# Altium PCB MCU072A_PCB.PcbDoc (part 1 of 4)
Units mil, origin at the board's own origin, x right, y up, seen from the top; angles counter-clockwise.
Board outline 2661.1 x 1953.35 mil, 8 copper layers (Top Layer, Mid-Layer 2, Mid-Layer 3, Mid-Layer 4, Mid-Layer 5, Mid-Layer 6, Mid-Layer 7, Bottom Layer), stack 61.2 mil thick; 186 components, 165 nets, 716 pads, 419 vias.
Unrouted connection lines stored in the file: 1.
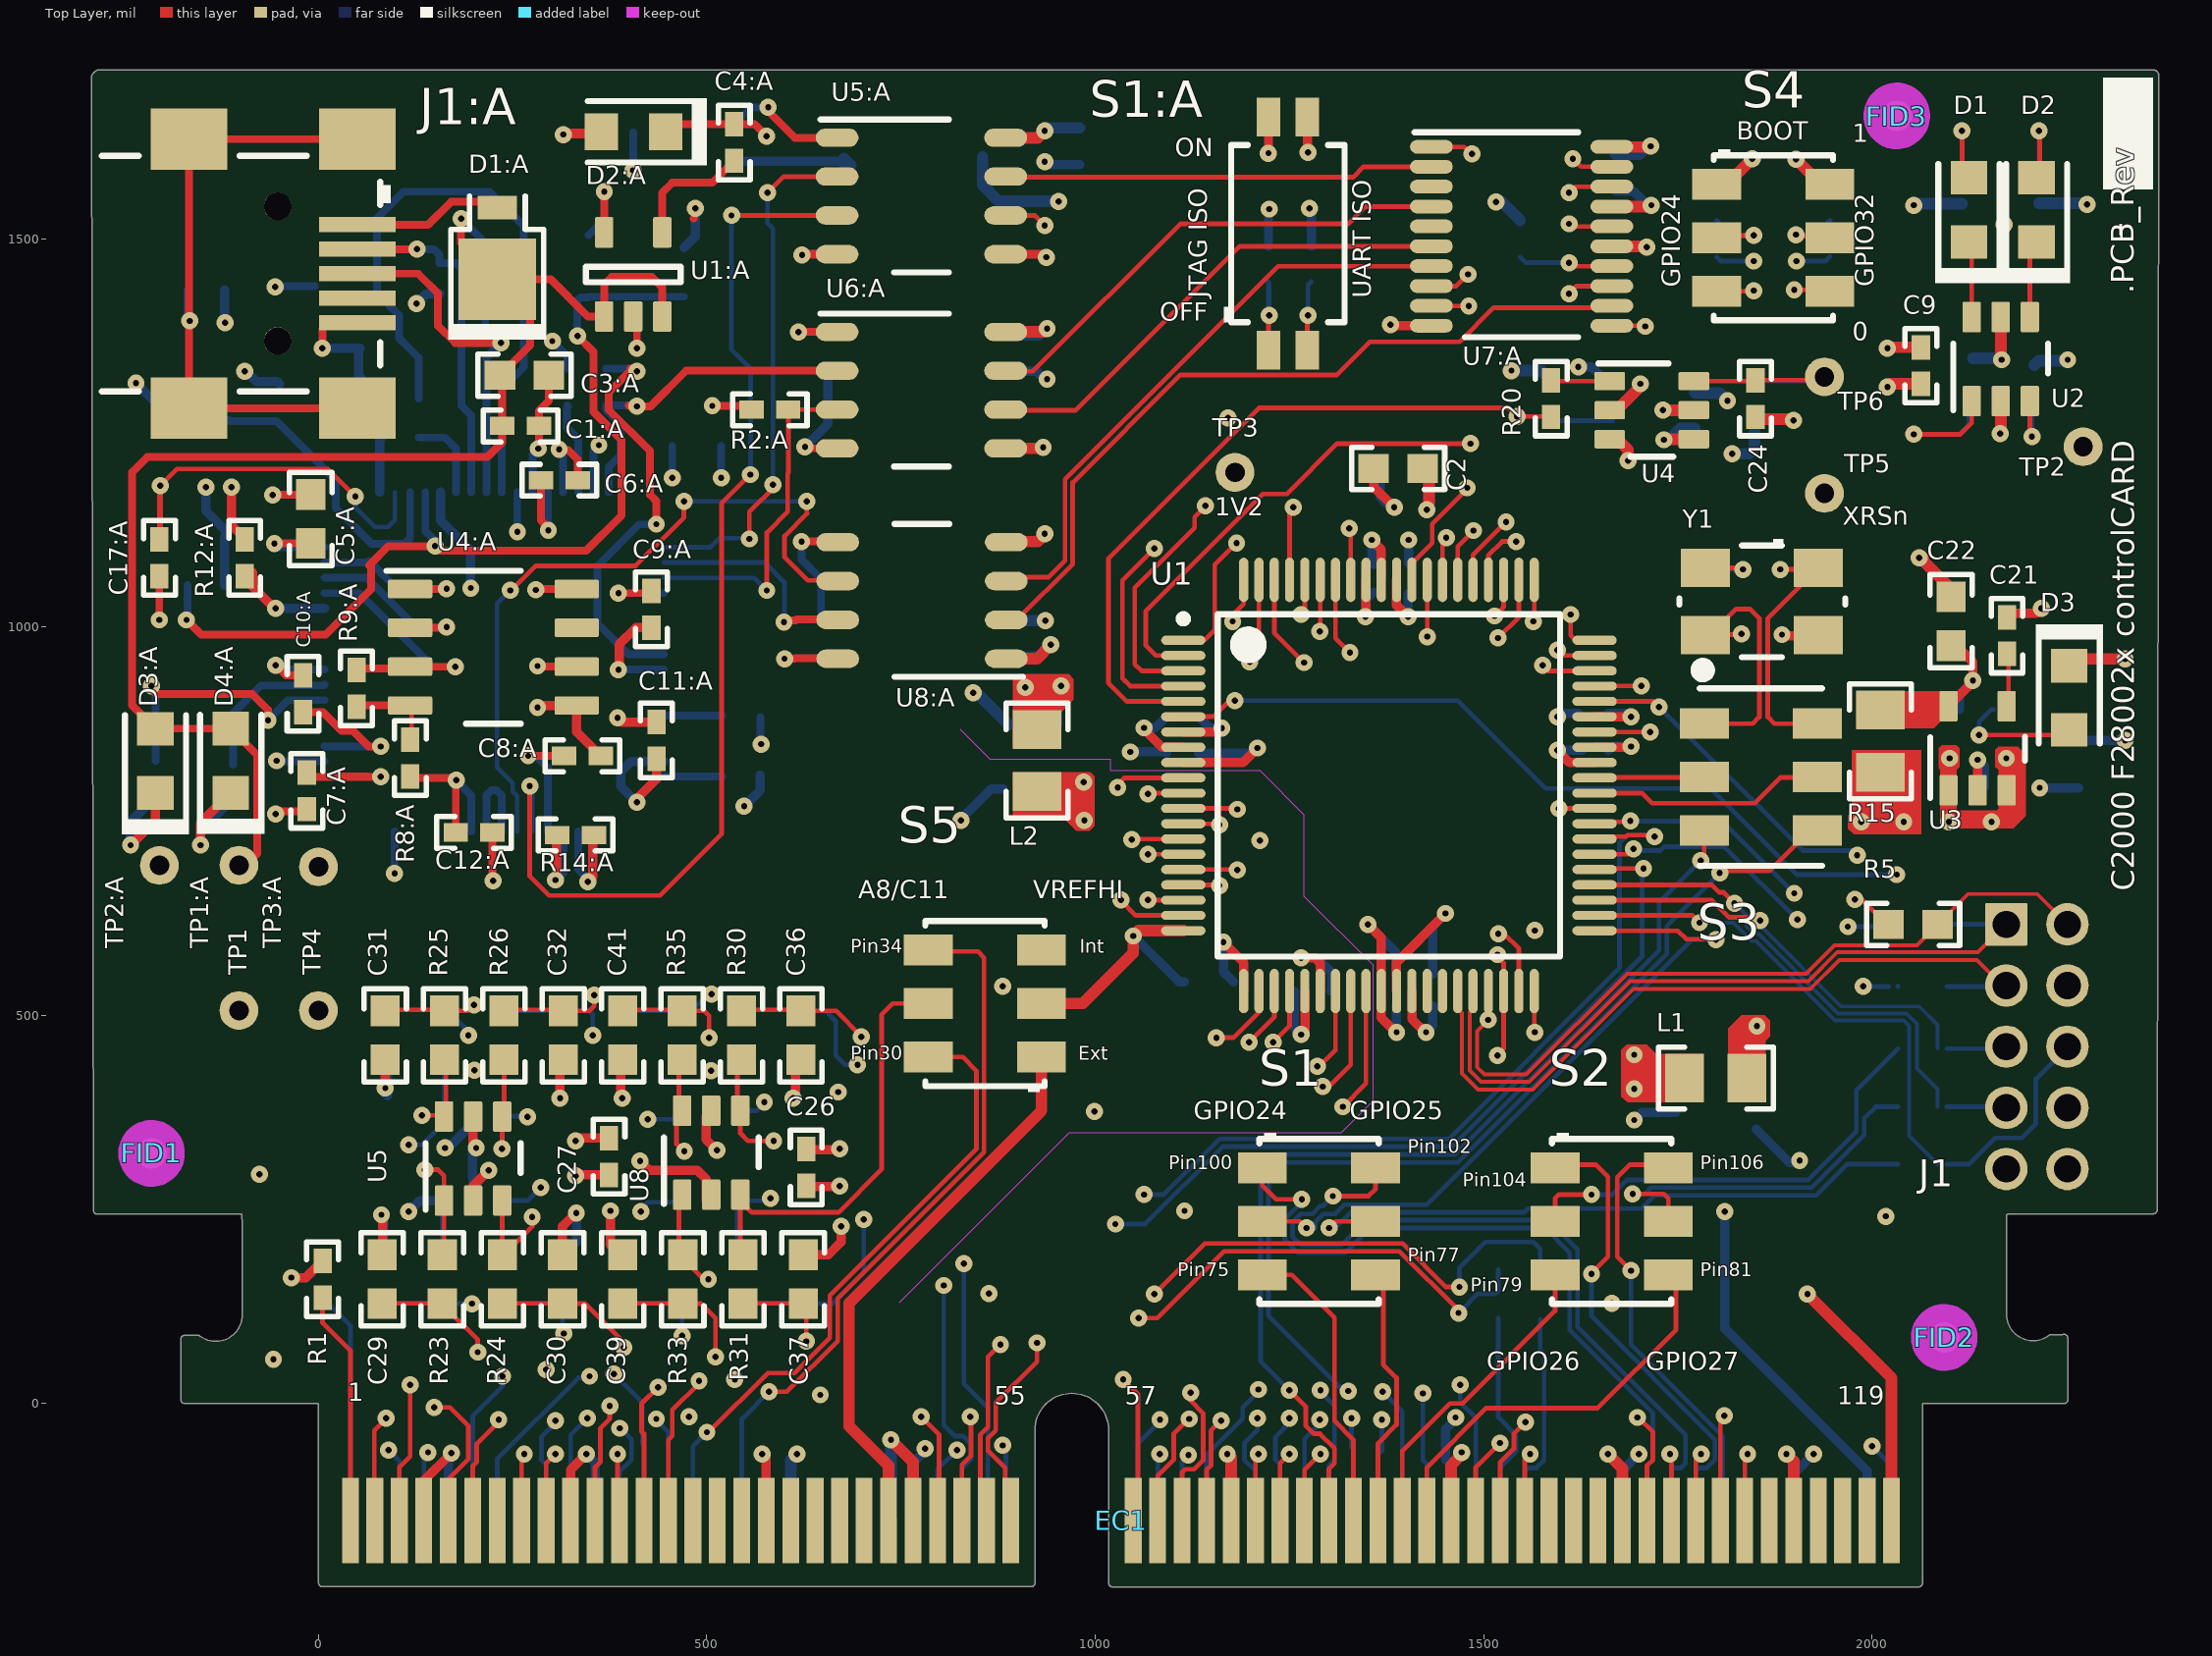
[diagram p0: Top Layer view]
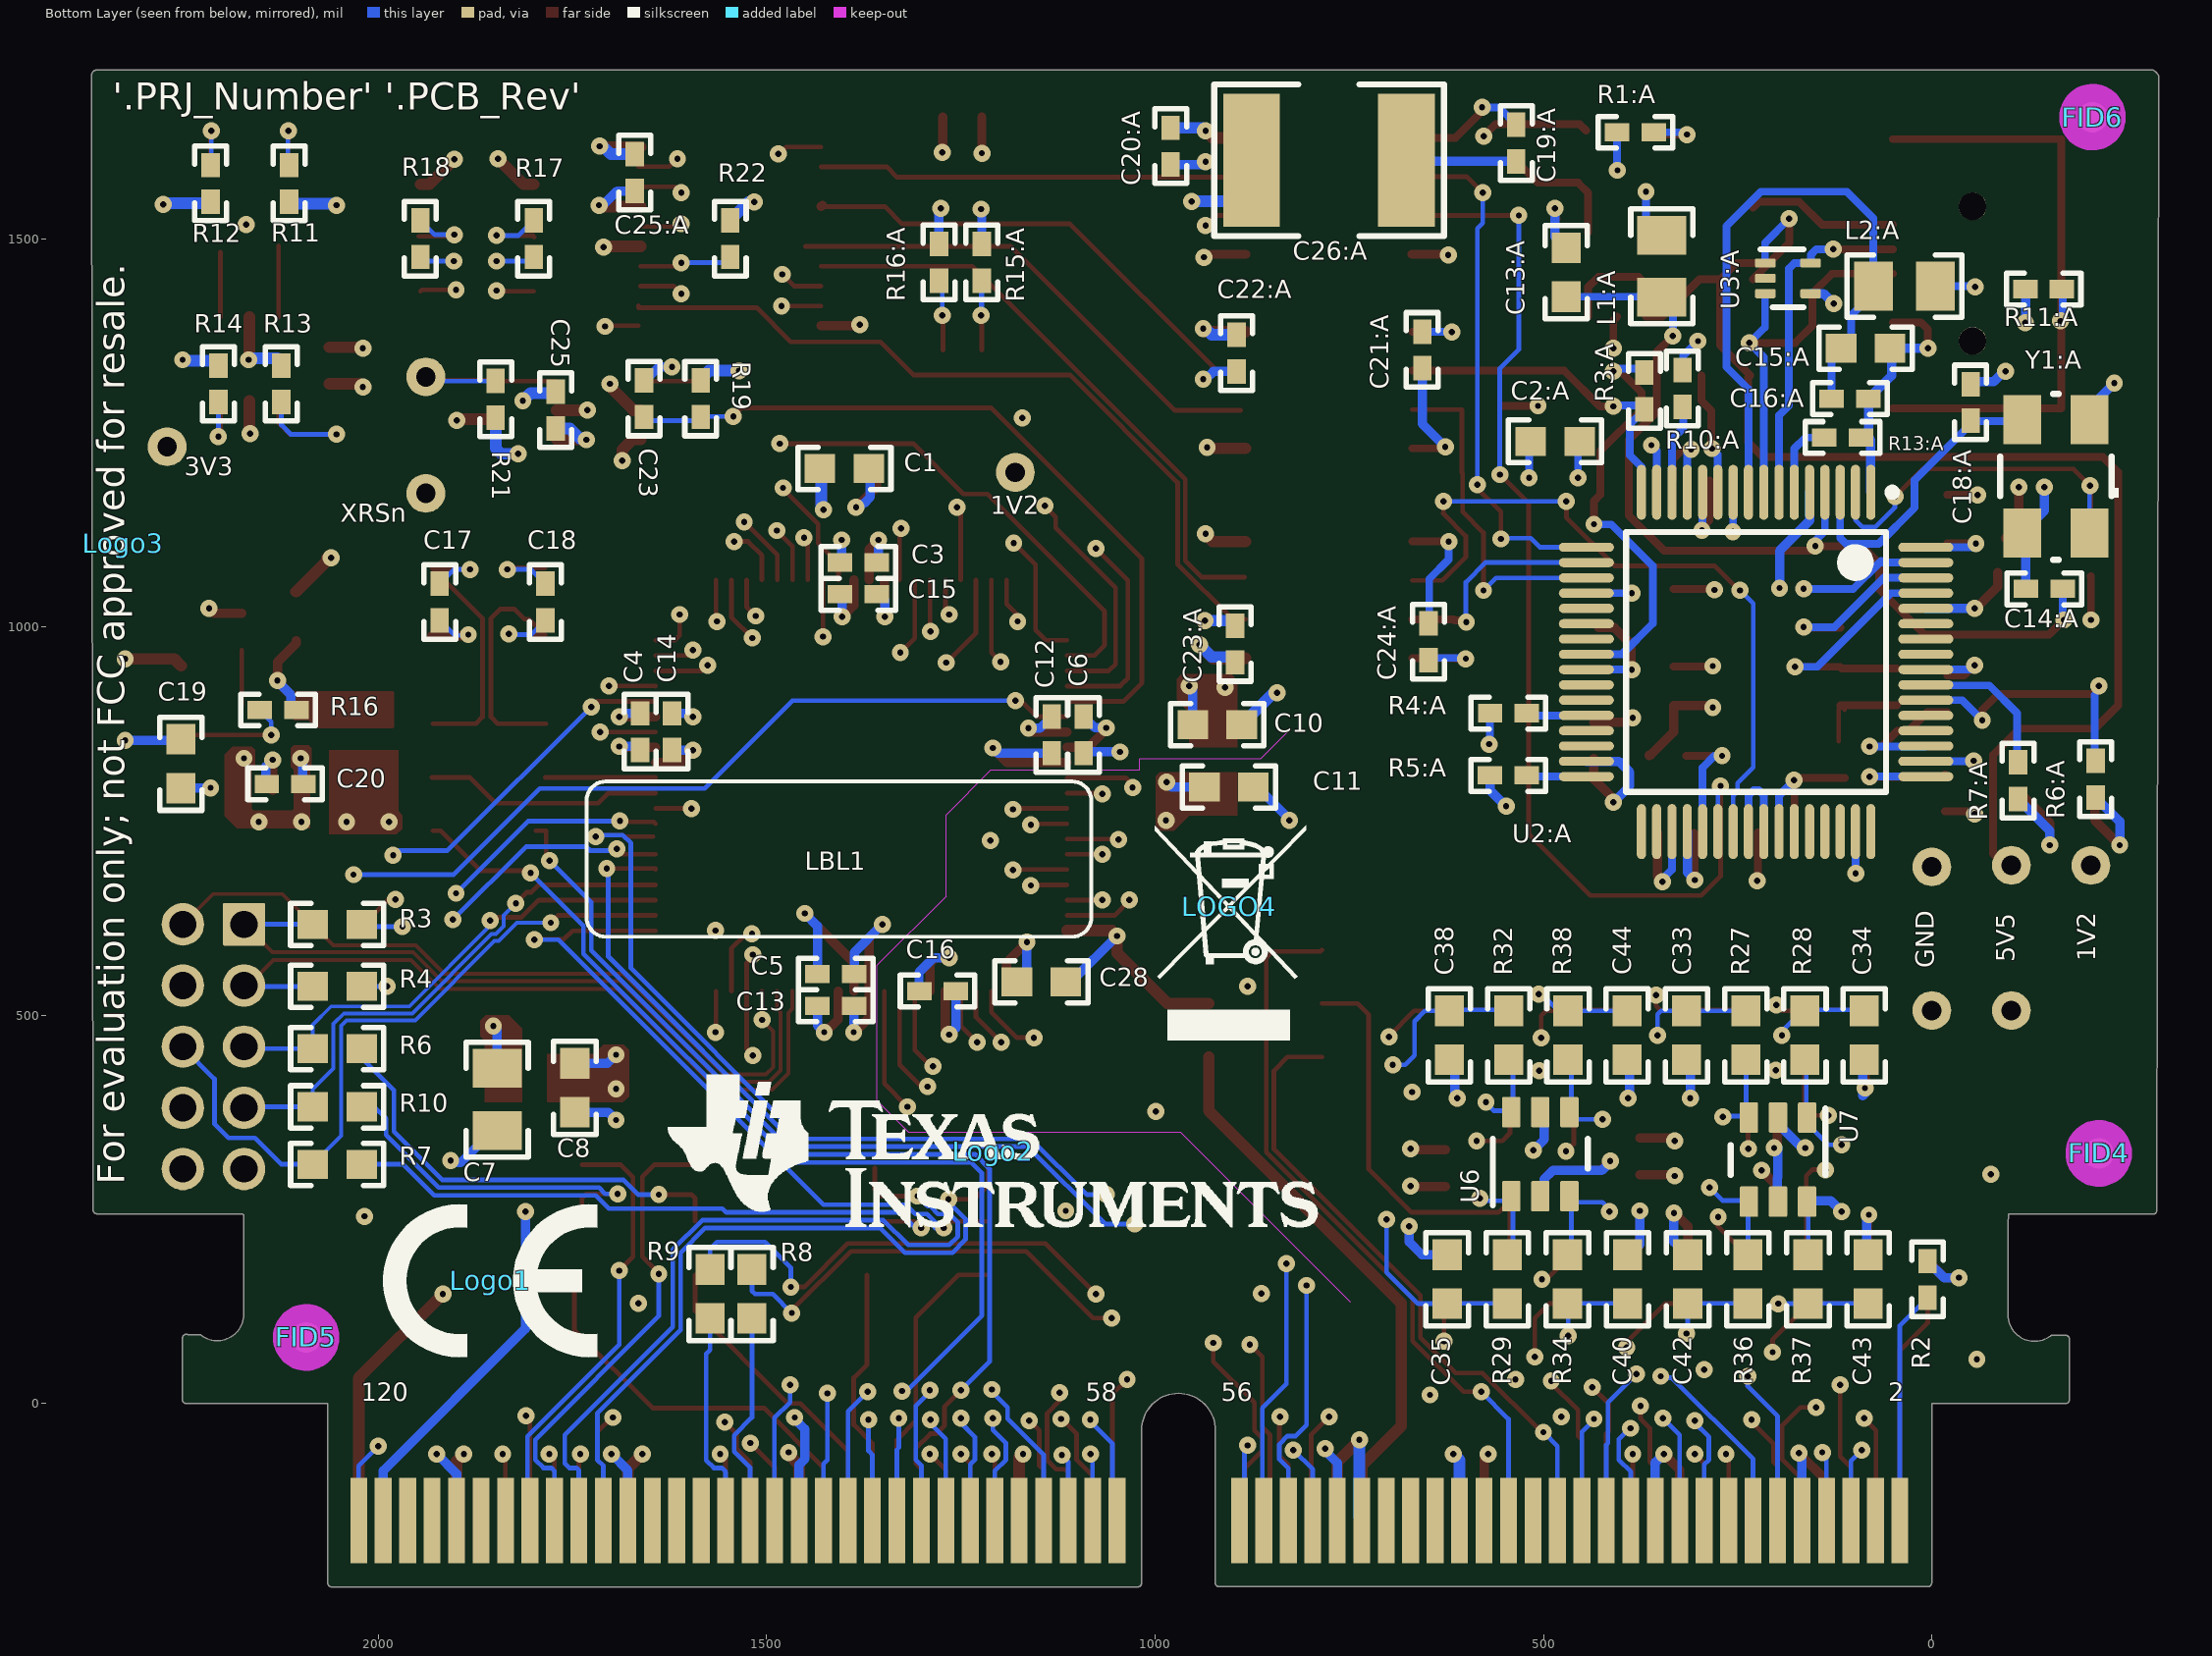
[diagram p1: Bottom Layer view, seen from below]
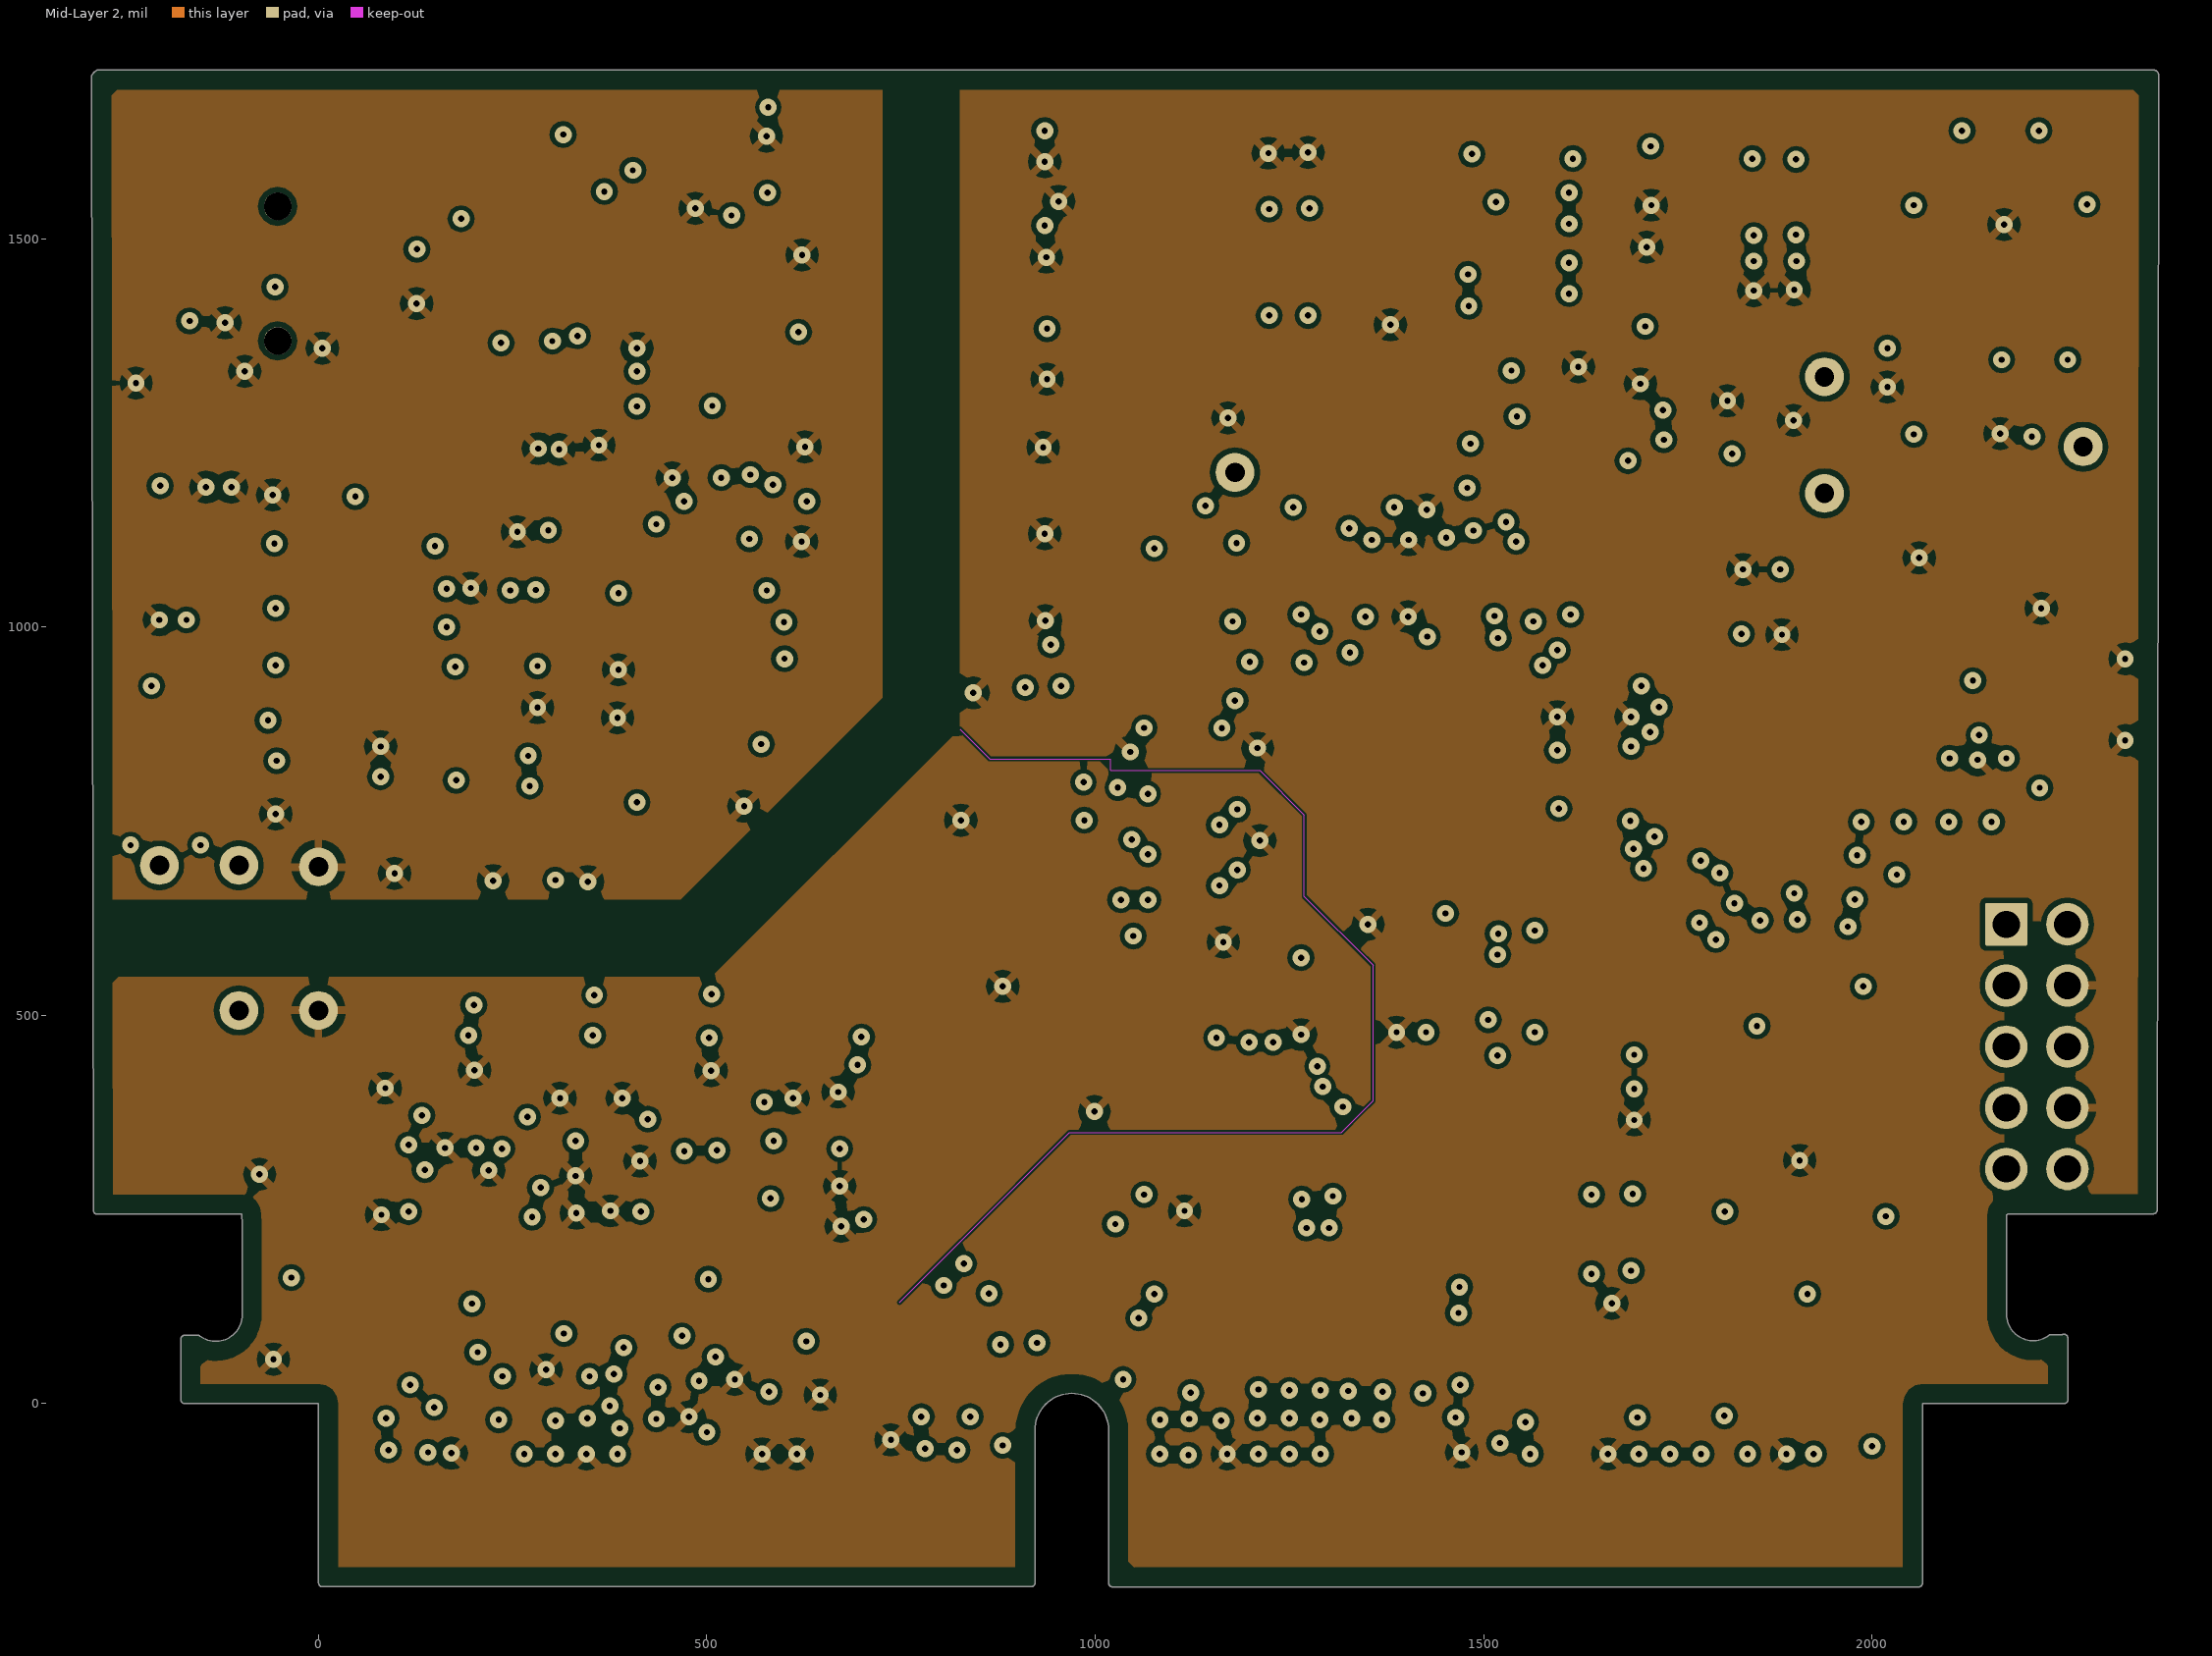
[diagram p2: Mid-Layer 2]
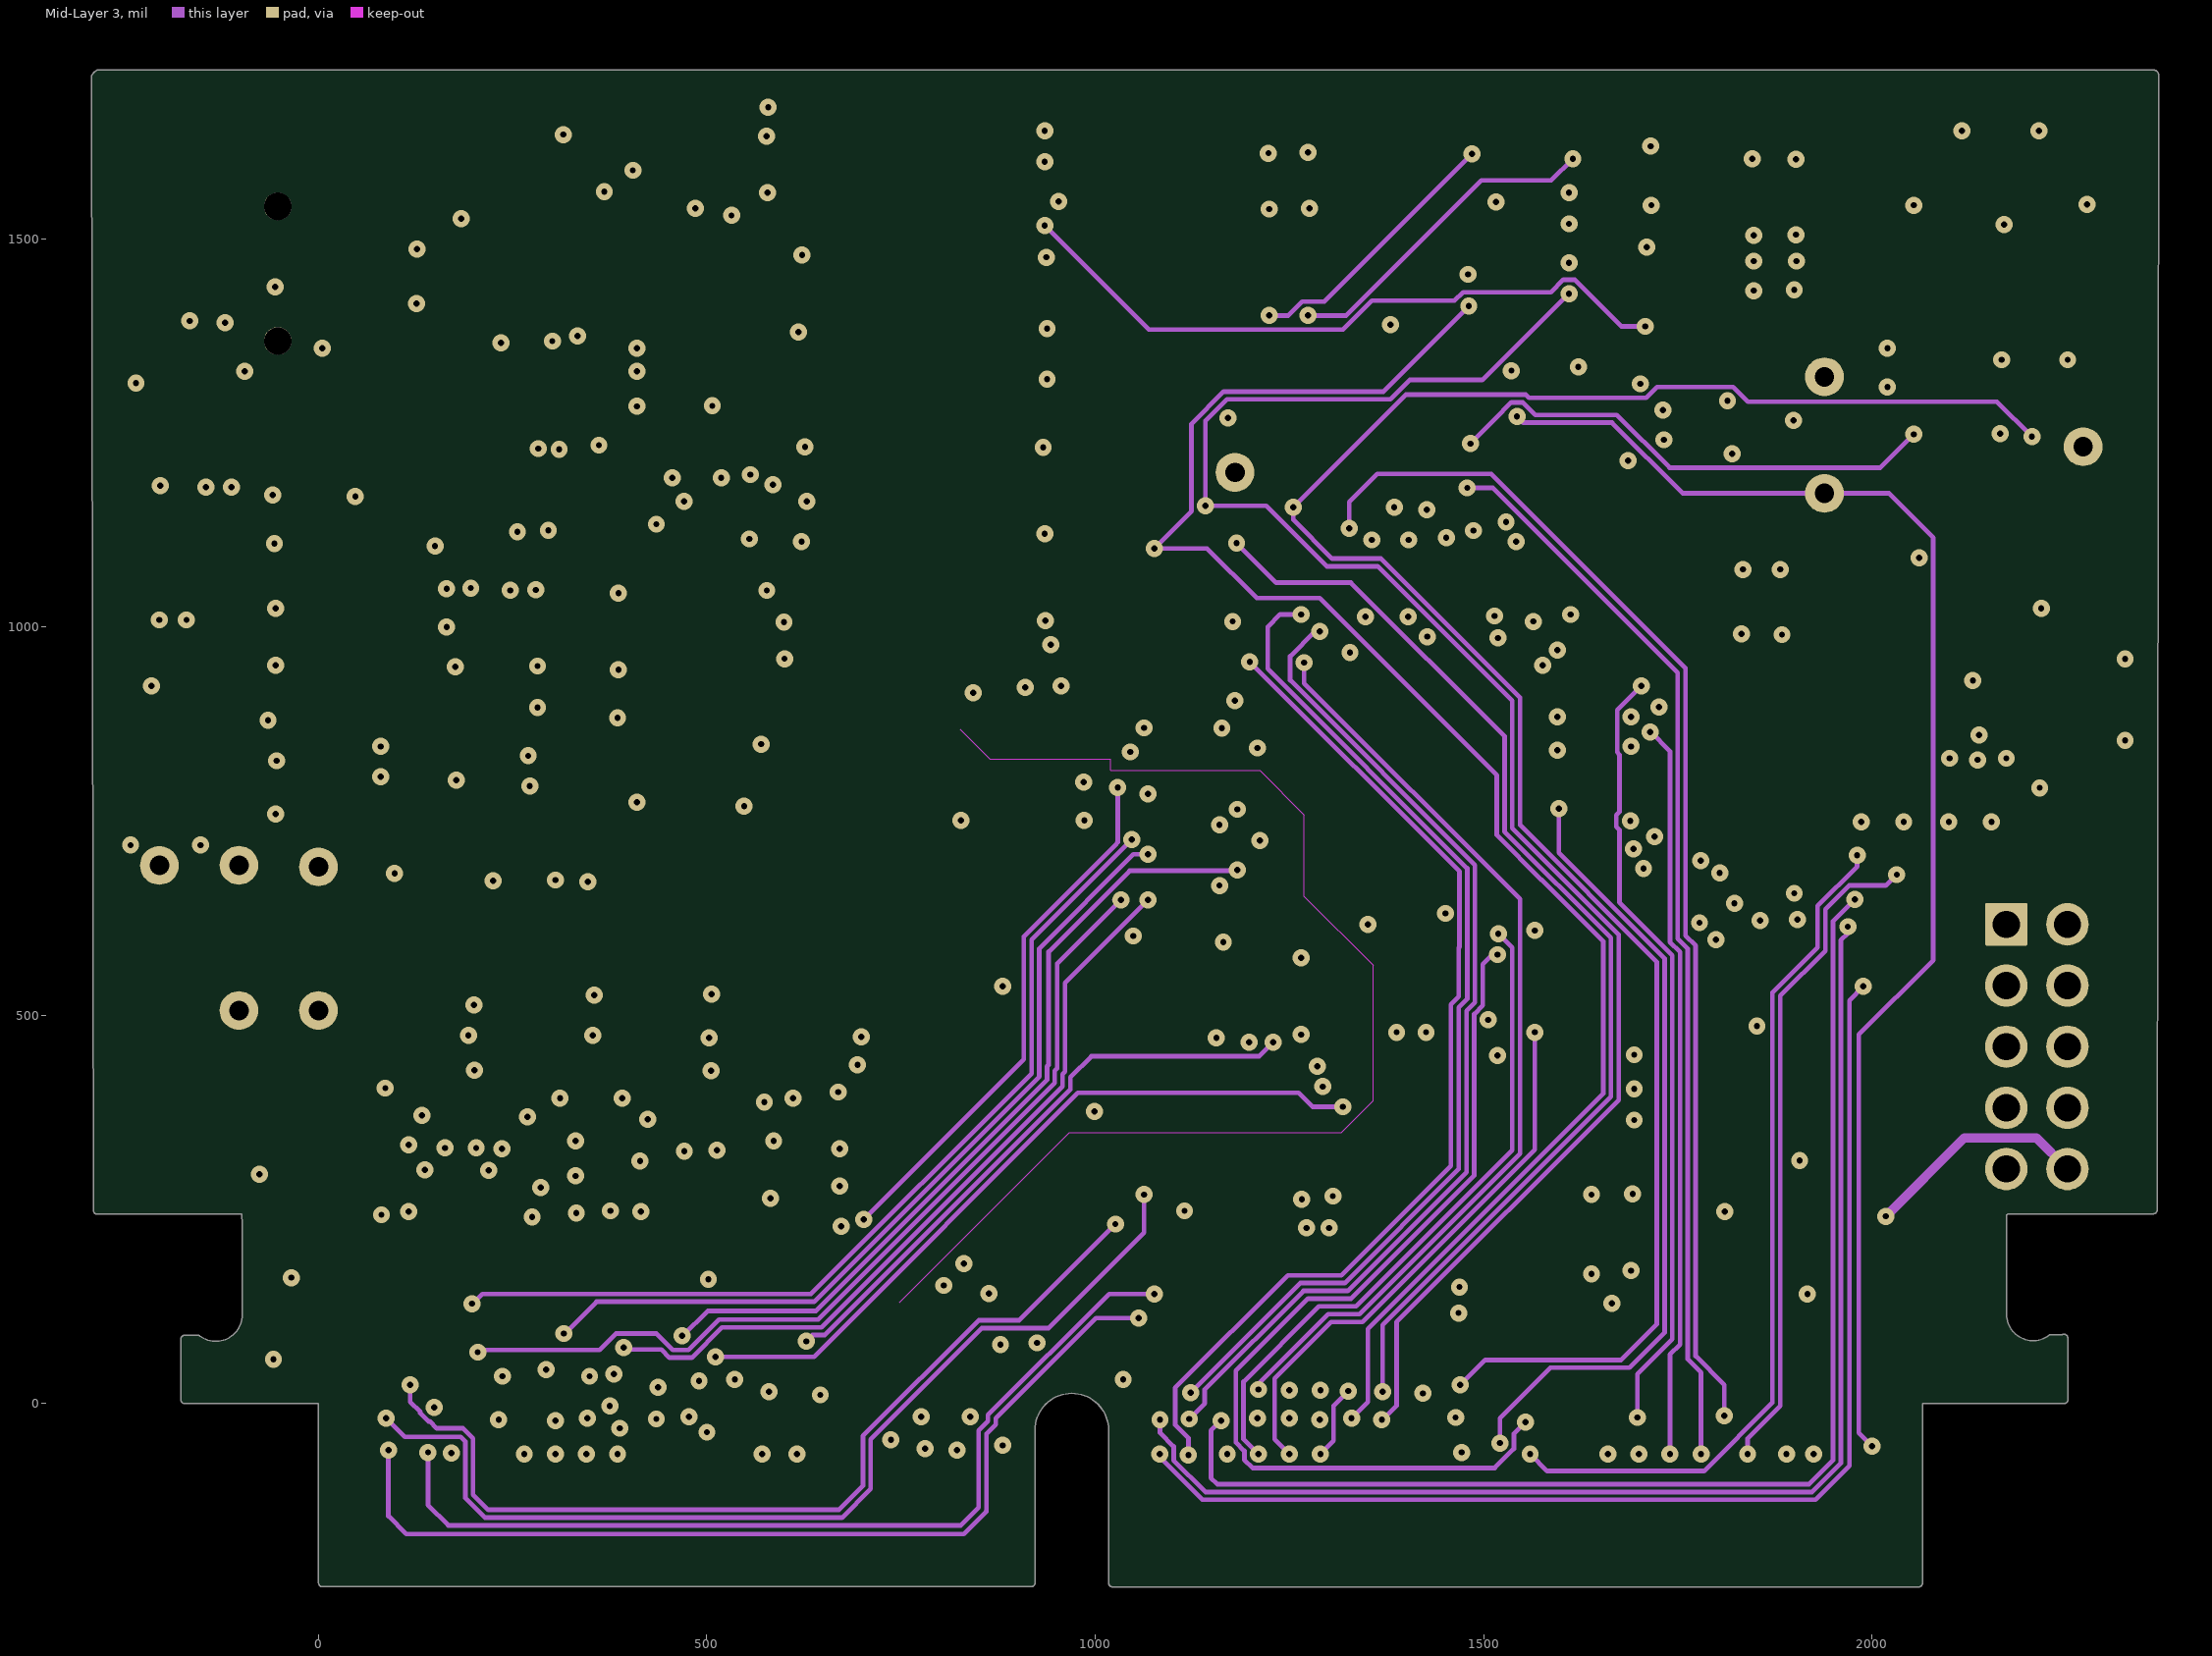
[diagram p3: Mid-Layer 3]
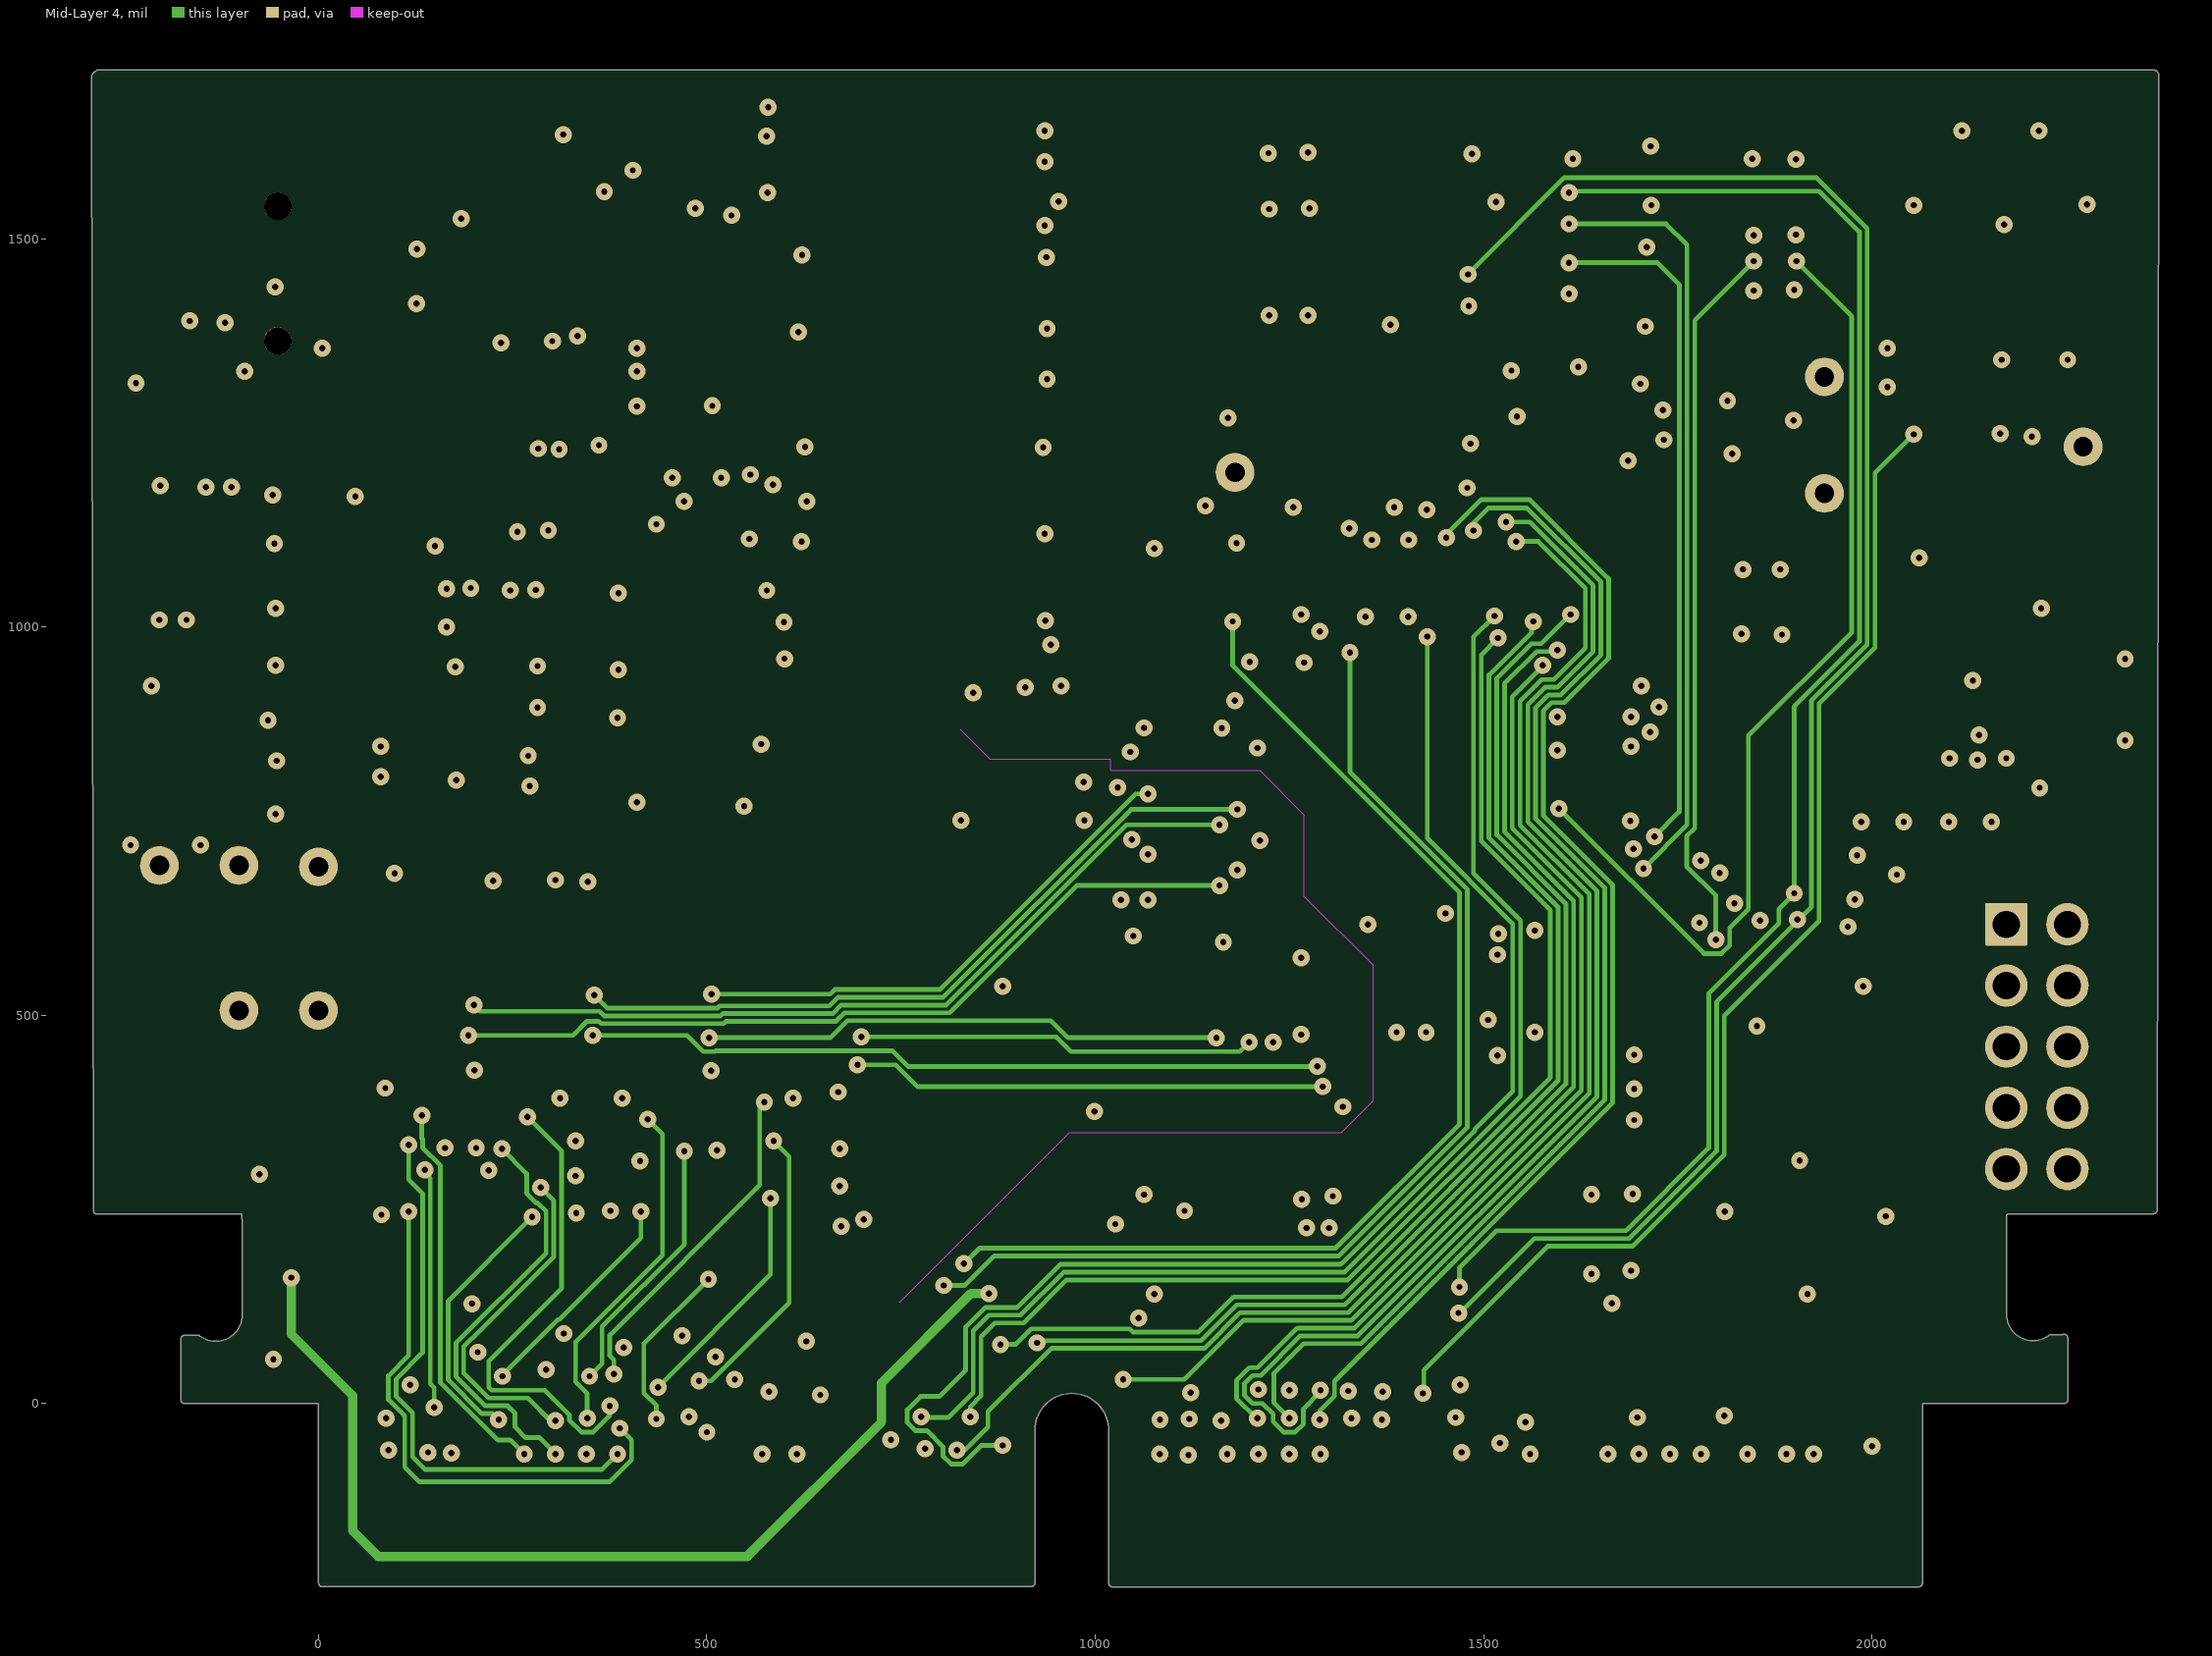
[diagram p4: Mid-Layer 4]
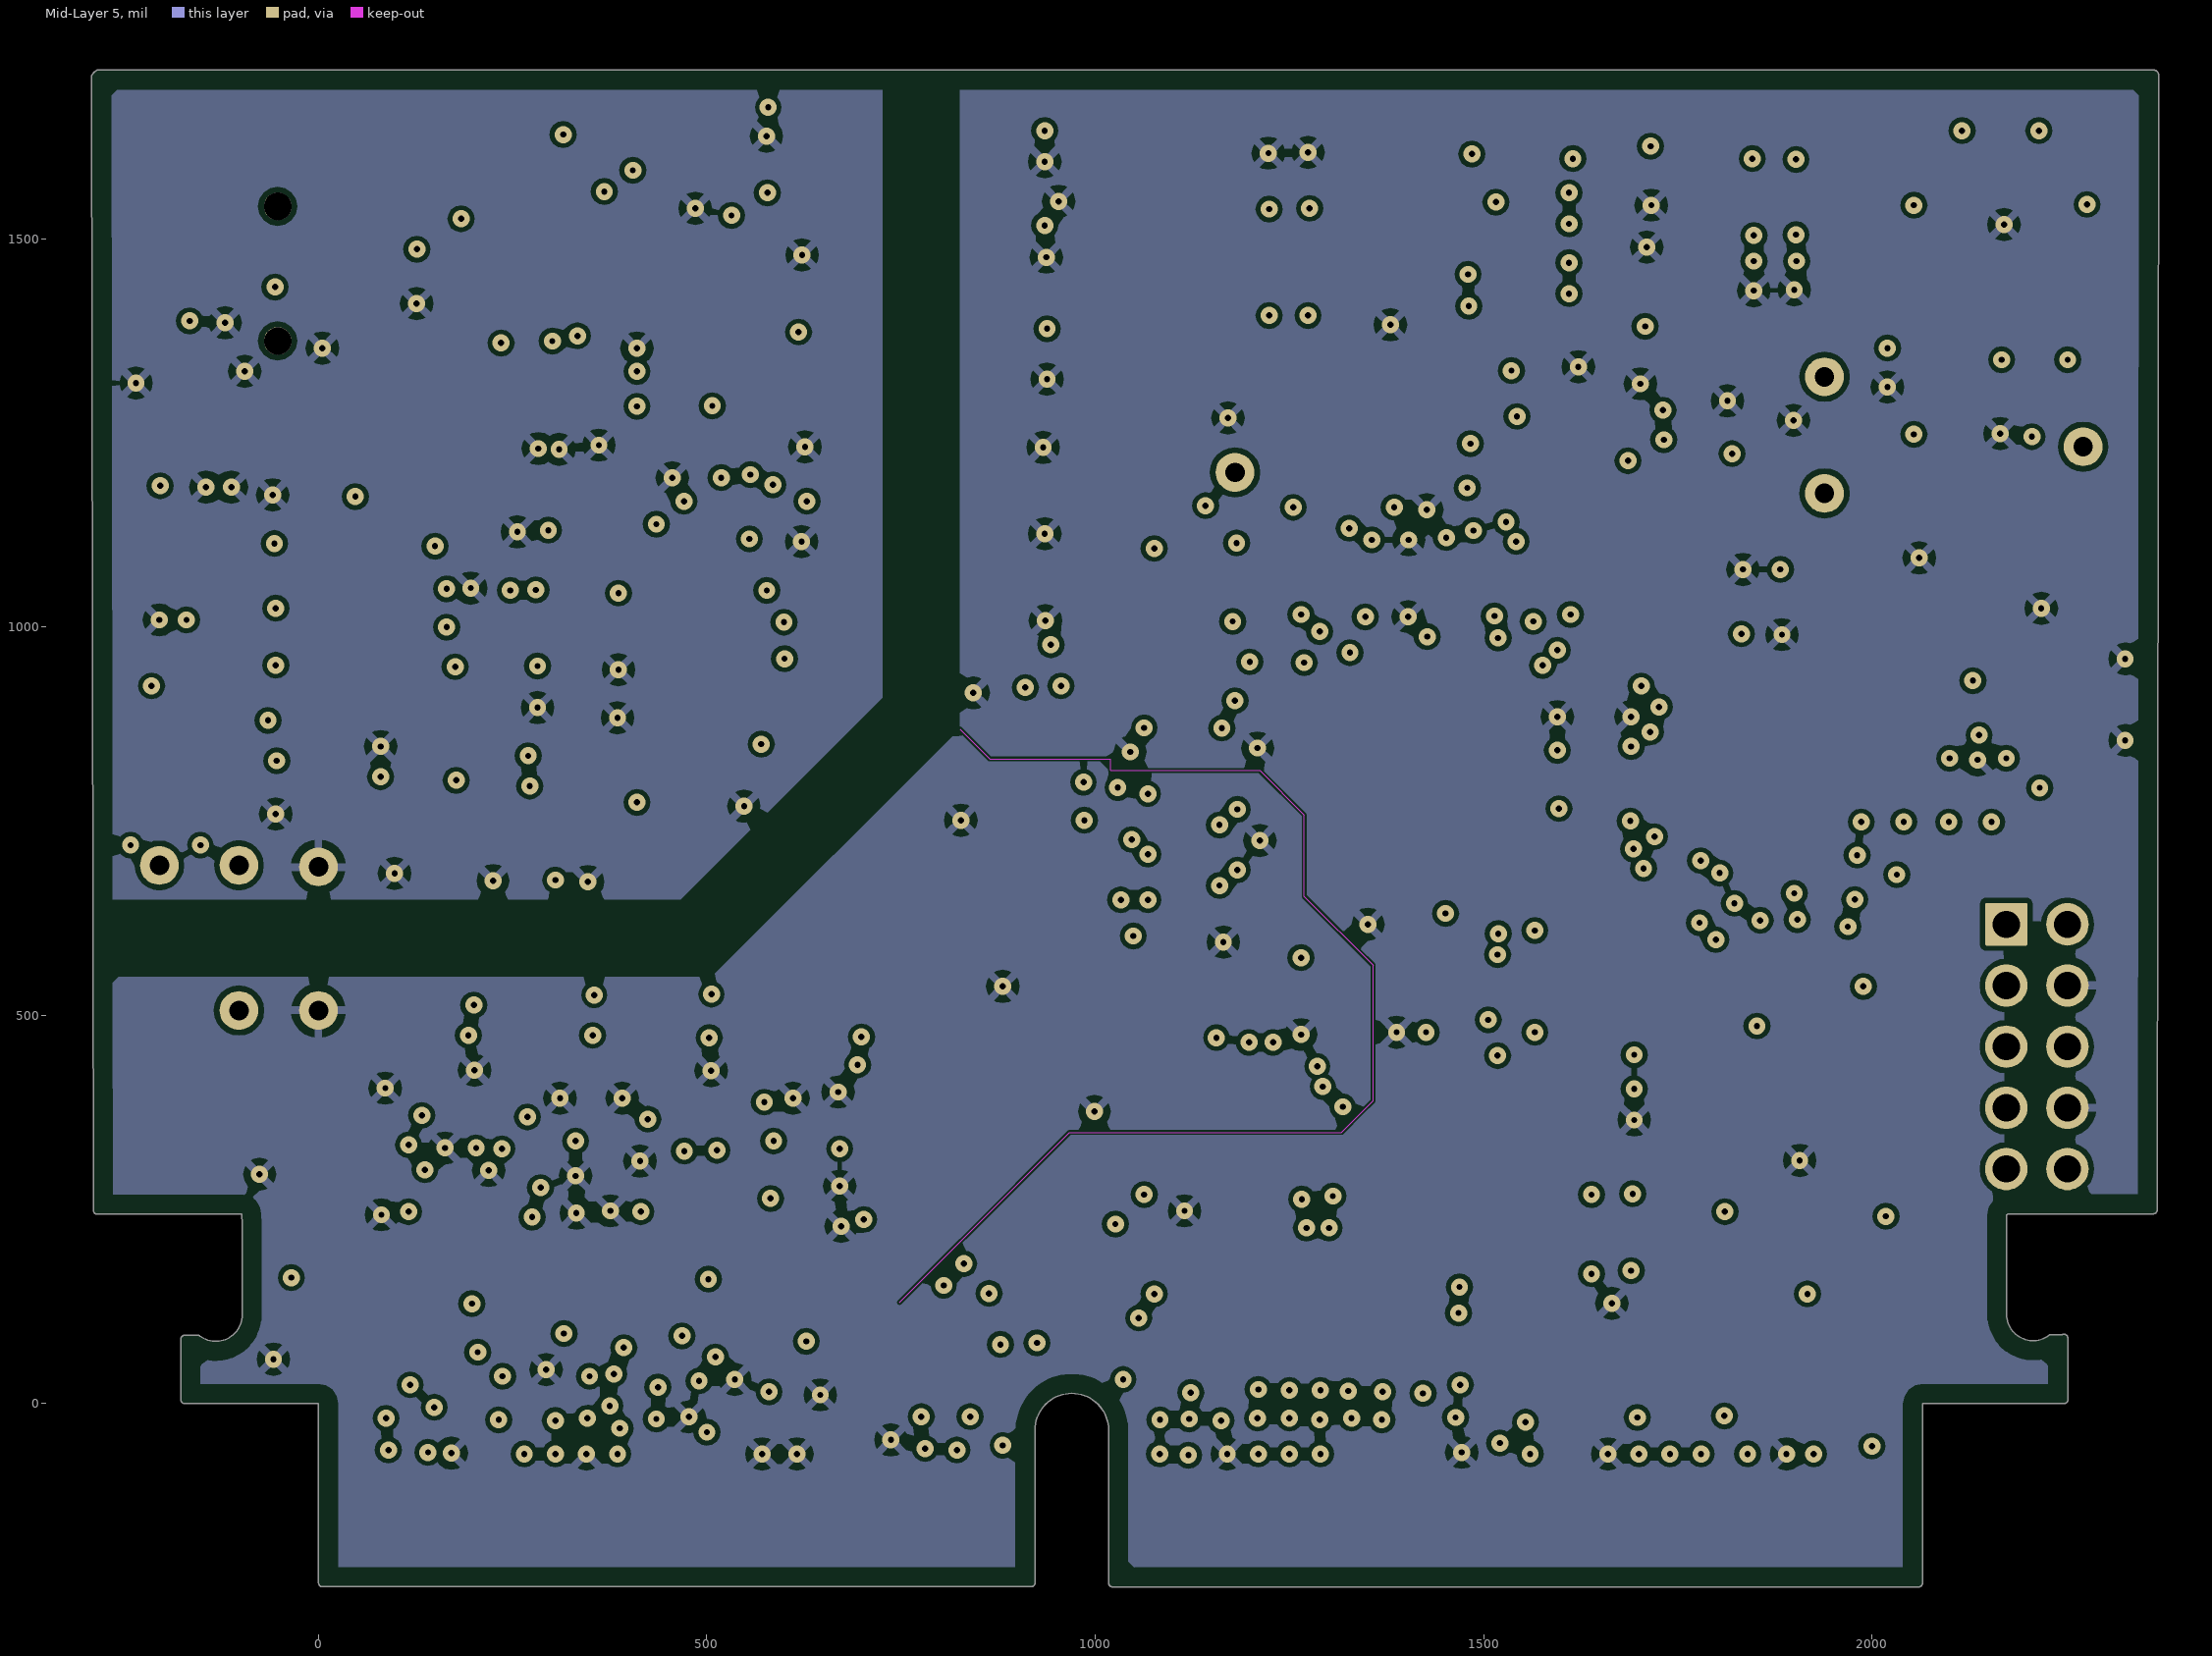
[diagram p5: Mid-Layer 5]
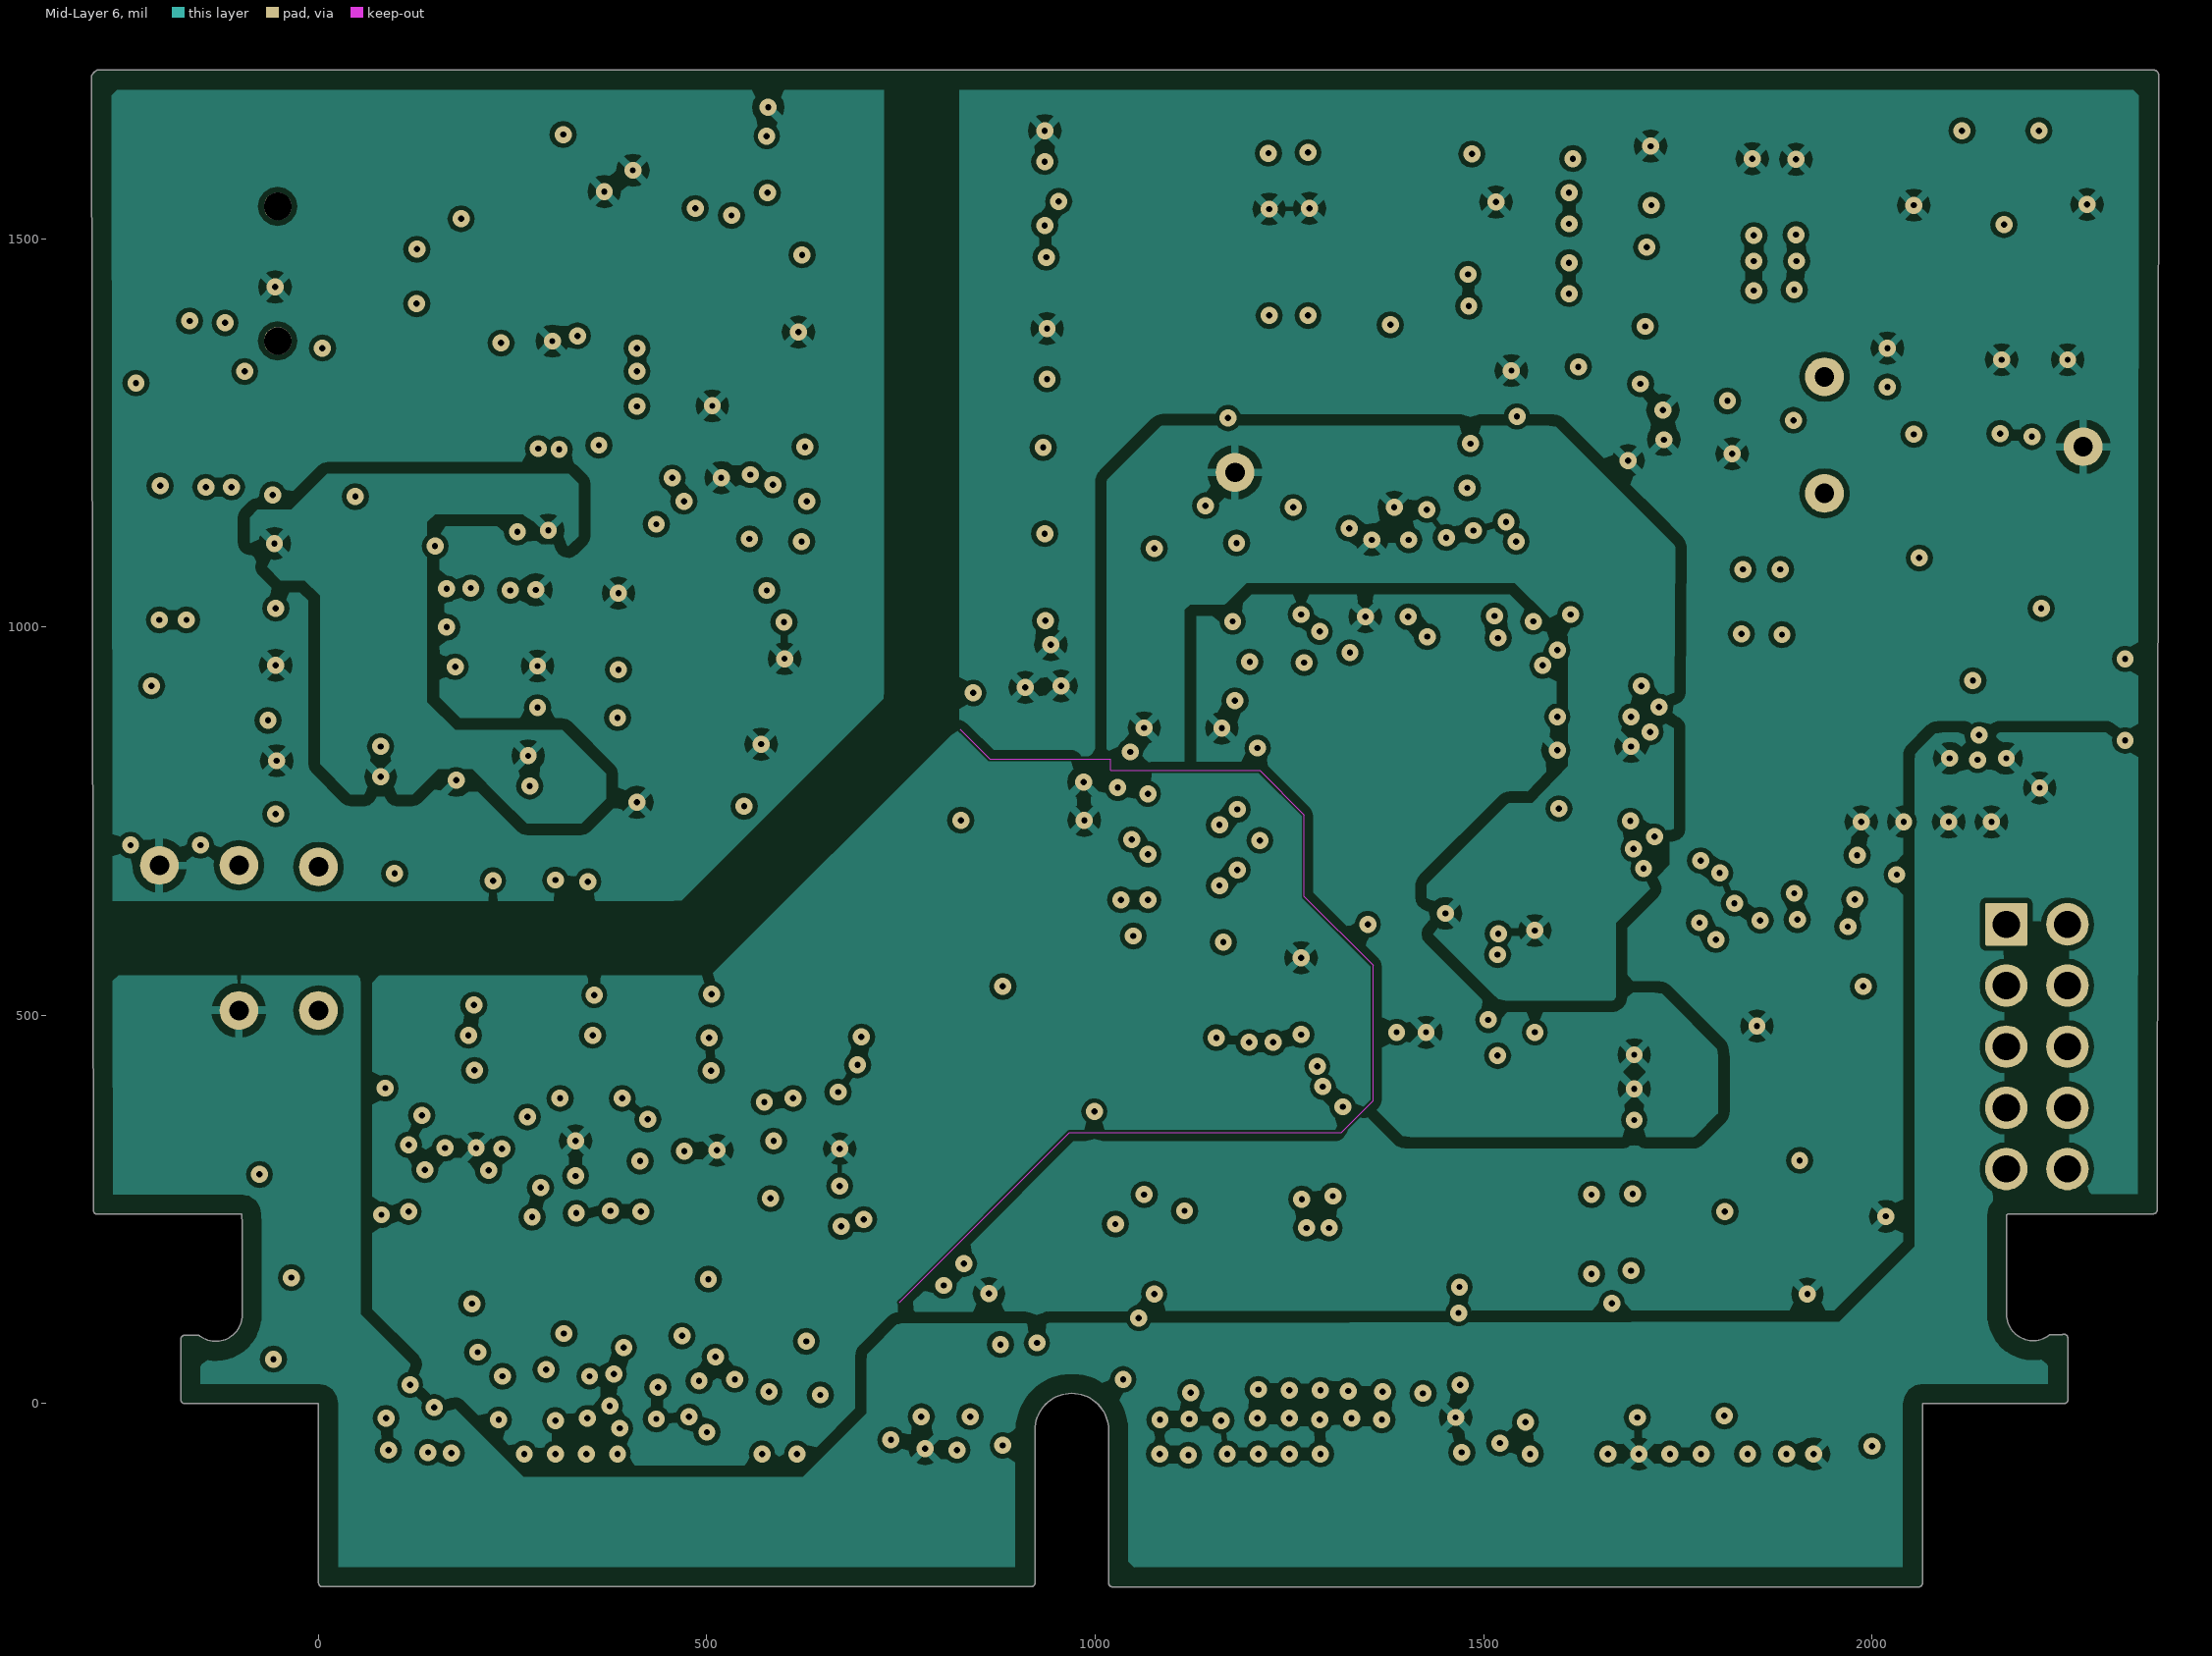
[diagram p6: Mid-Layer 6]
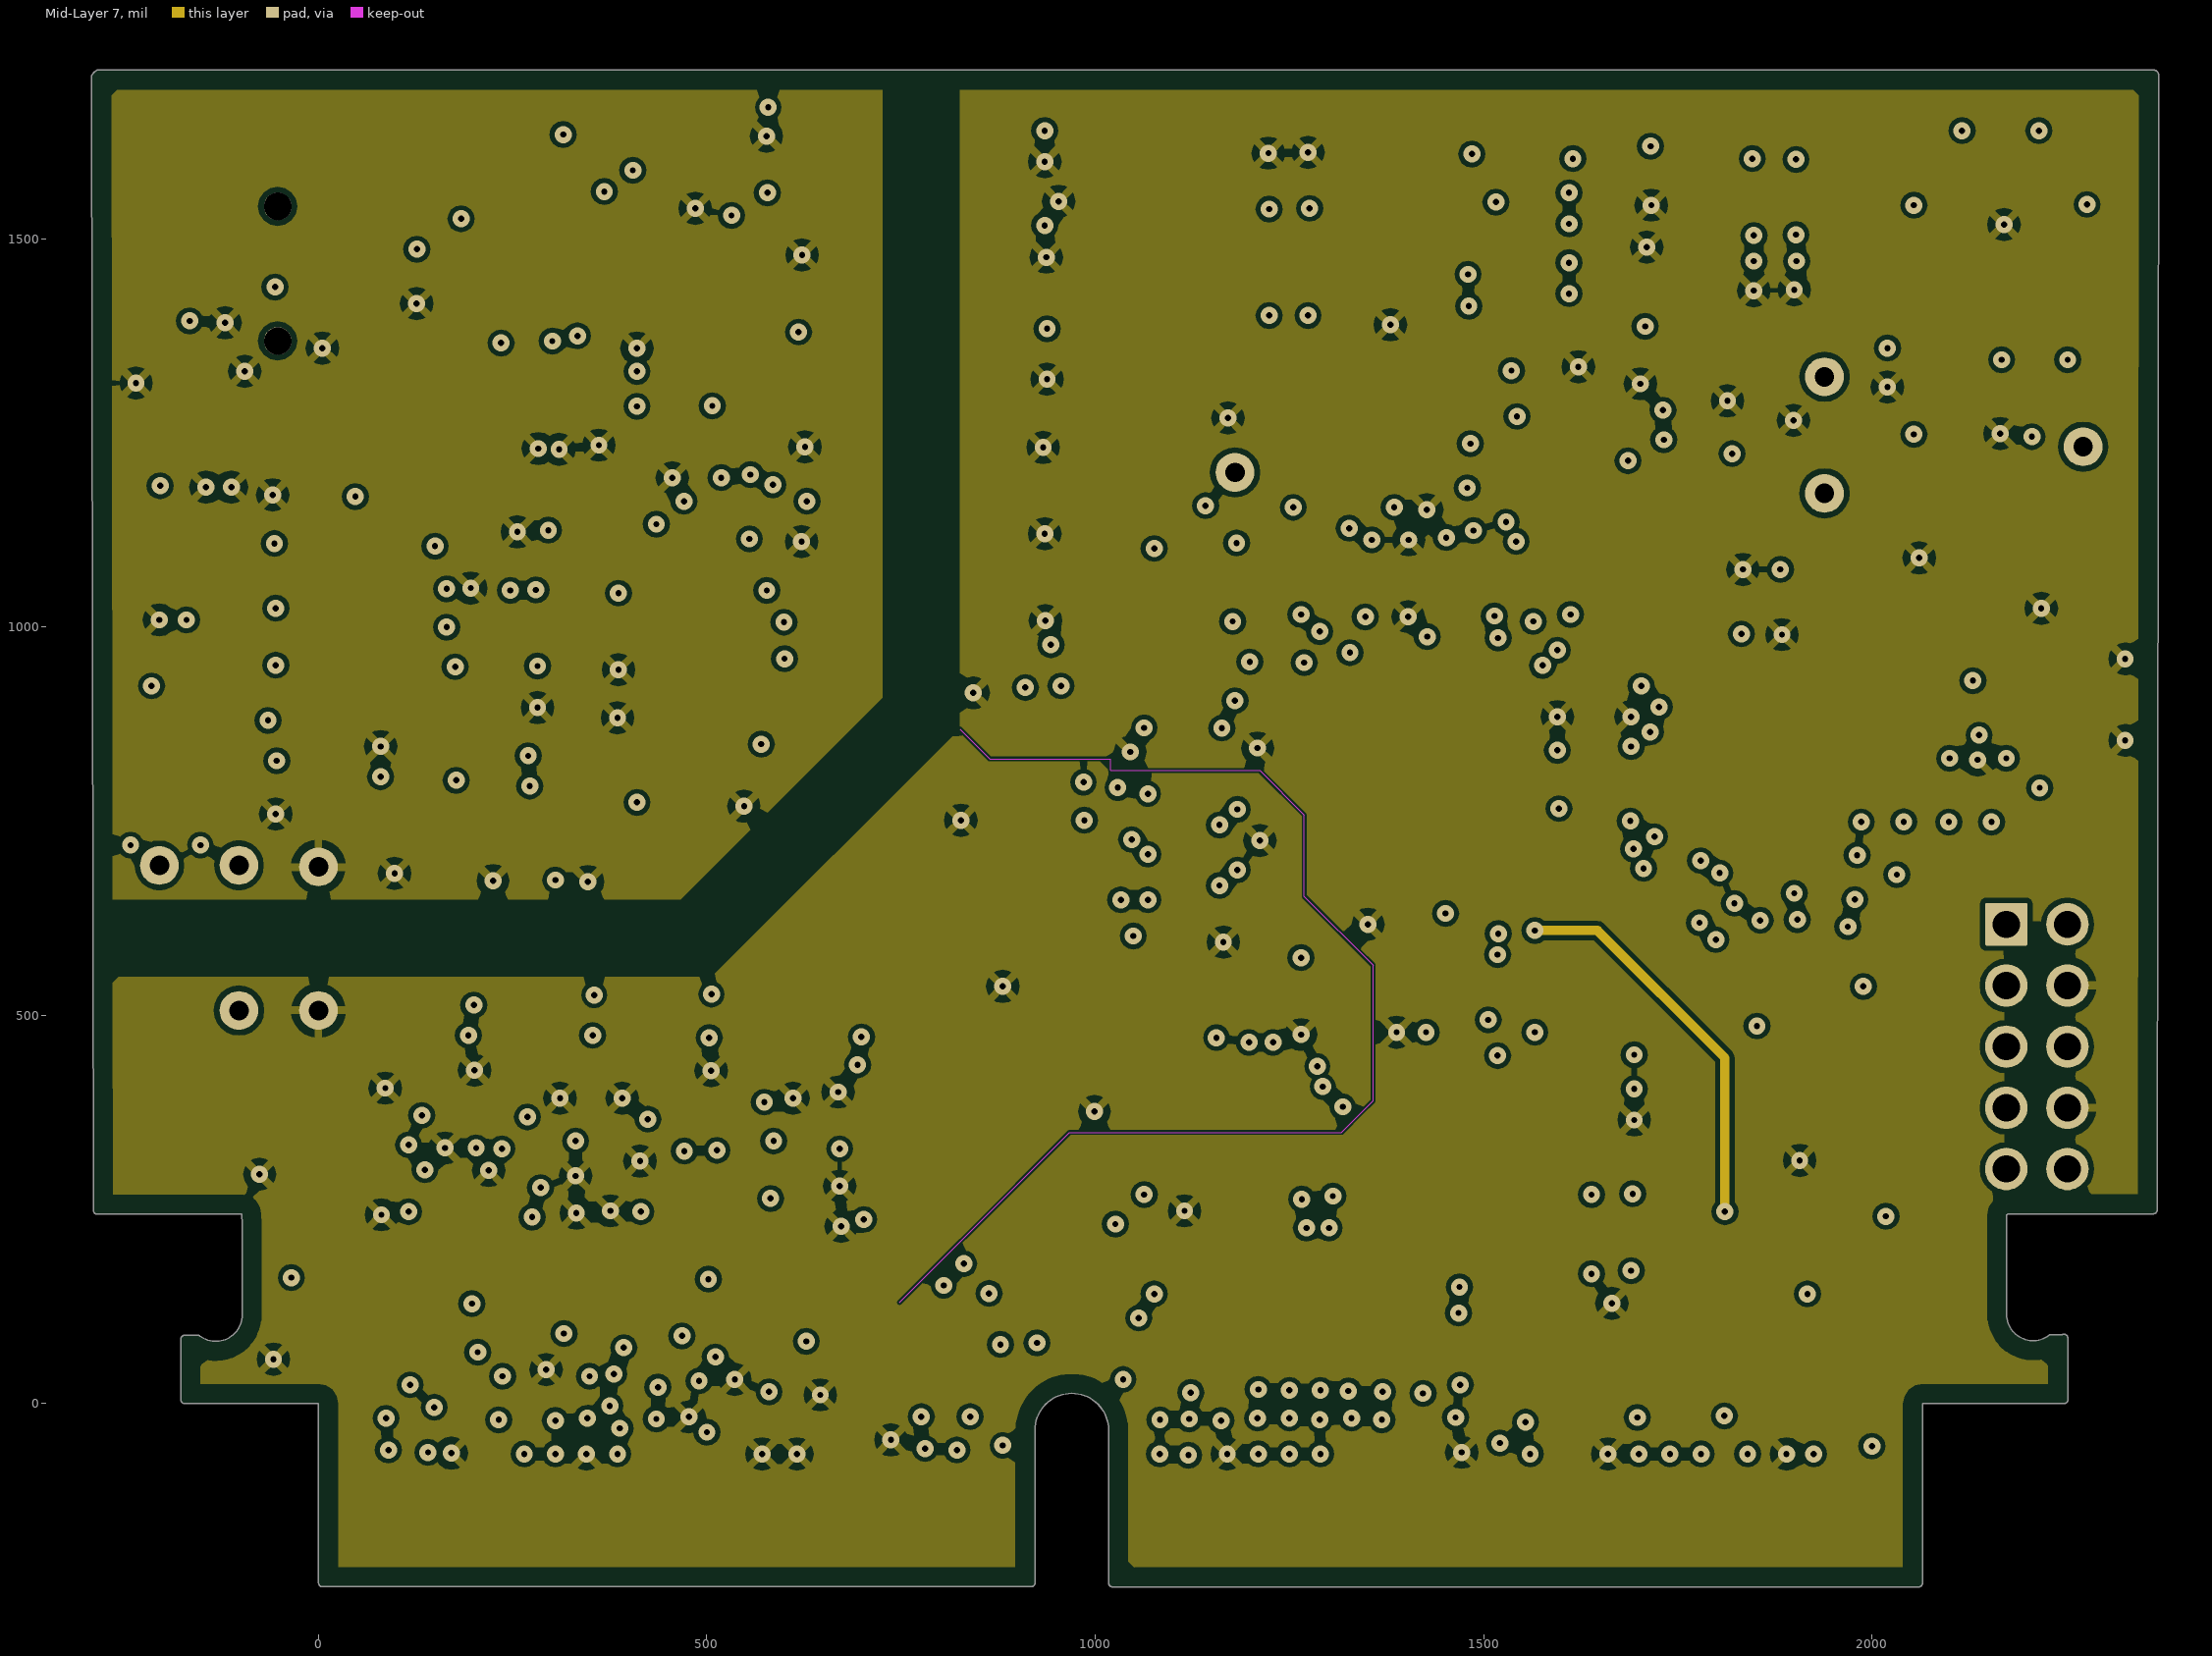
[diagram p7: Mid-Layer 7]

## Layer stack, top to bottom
Top Solder: solder mask 0.5, Solder Resist, Dk 3.5
Top Layer: signal copper 1.4
Dielectric1: prepreg 5, FR-4 High Tg, Dk 4.2
Mid-Layer 2: signal copper 1.4
Dielectric2: core 10, FR-4 High Tg, Dk 4.2
Mid-Layer 3: signal copper 1.4
Dielectric3: prepreg 5, FR-4 High Tg, Dk 4.2
Mid-Layer 4: signal copper 1.4
Dielectric4: core 10, FR-4 High Tg, Dk 4.2
Mid-Layer 5: signal copper 1.4
Dielectric5: prepreg 5, FR-4 High Tg, Dk 4.2
Mid-Layer 6: signal copper 1.4
Dielectric6: core 10, FR-4 High Tg, Dk 4.2
Mid-Layer 7: signal copper 1.4
Dielectric7: prepreg 5, FR-4 High Tg, Dk 4.2
Bottom Layer: signal copper 1.4
Bottom Solder: solder mask 0.5, Solder Resist, Dk 3.5

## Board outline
-177.19,4.84 ccw(c-172.19,4.83) -171.02,-0.04 0.06,-0.04 0.06,-231.05 ccw(c5.07,-231.05) 5.9,-236 917.51,-236 ccw(c917.51,-230.98) 922.53,-230.98 ccw(c917.77,-230.97) 922.31,-229.57 922.32,-229.56 922.32,-35.08 922.42,-34.1 cw(c969.9,-34.49) 1017.39,-34.1 1017.39,-231.27 ccw(c1022.39,-231.28) 1018.85,-234.82 1018.86,-234.81 ccw(c1022.51,-231.22) 1022.46,-236.35 2060.22,-236.28 ccw(c2060.22,-231.26) 2065.23,-231.26 2065.16,-230.44 2065.16,-0.11 2247.39,-0.11 ccw(c2247.39,4.91) 2252.41,4.91 ccw(c2247.65,4.92) 2252.2,6.32 2252.2,6.33 2252.2,84.13 ccw(c2247.2,84.13) 2245.21,88.73 2245.21,88.74 2230.93,88.74 ccw(c2230.91,83.8) 2227.9,87.72 2227.9,87.73 cw(c2207.4,114.83) 2173.42,114.71 2173.42,242.73 2174.88,244.19 2362.35,244.19 ccw(c2362.35,249.2) 2365.89,245.66 2365.9,245.66 ccw(c2362.33,249.29) 2367.42,249.26 2367.42,249.27 2369,1709.72 ccw(c2362.92,1710.82) 2363.01,1717 -284.72,1717 ccw(c-279.84,1704.84) -292,1709.72 -289.73,248.71 ccw(c-284.72,248.71) -284.72,243.7 -98.73,243.7 -98.73,238.74 ccw(c-93.74,238.73) -98.32,236.75 -98.32,115.84 cw(c-124,114.26) -98.27,113.93 cw(c-132.25,113.92) -152.76,86.83 ccw(c-155.74,82.96) -155.78,87.84 -172.11,87.84 ccw(c-172.15,82.91) -175.66,86.37 ccw(c-172.11,82.73) -177.19,82.76

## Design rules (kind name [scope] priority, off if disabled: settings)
AcuteAngle [Not IsPoly] p1: minimum=4.50000000000000E+0001 checktracksonly=TRUE
AssemblyTestPointUsage [All] p1: valid=2
BoardOutlineClearance BoardOutlineClearance_MountingHoles [OnCopper and InComponentClass('Mounting Holes')] p1: gap=40 ignorepadtopadclearanceinfootprint=FALSE
BoardOutlineClearance BoardOutlineClearance_Poly [OnCopper and IsPoly] p2: gap=25 ignorepadtopadclearanceinfootprint=FALSE
BoardOutlineClearance [OnCopper and Not InComponentClass('Logo') and not InComponentClass('FiducialMark') and not InComponent ('EC1') and not InPoly and not InRegion(-350,-150,2400,2025)] p3: gap=40 ignorepadtopadclearanceinfootprint=FALSE except(30: Arc-OutlineEdge Track-OutlineEdge SMDPad-OutlineEdge THPad-OutlineEdge Via-OutlineEdge Fill-OutlineEdge Poly-OutlineEdge Region-OutlineEdge Text-OutlineEdge)
Clearance Clearance_Keepouts [((IsTrack Or IsArc) And Not InPoly) And IsFree and IsKeepOut vs ((IsTrack Or IsArc) And Not InPoly) And IsFree and IsKeepOut] p1: gap=0 ignorepadtopadclearanceinfootprint=FALSE
Clearance Clearance_Boardedge_MountingHole [OnCopper and InComponentClass('Mounting Holes') vs IsKeepOut] p2: gap=30 ignorepadtopadclearanceinfootprint=FALSE except(0: Arc-Hole Track-Hole SMDPad-Hole THPad-Hole Via-Hole Fill-Hole Poly-Hole Region-Hole Text-Hole)
Clearance Clearance_Boardedge_Poly_1 [InPoly vs IsKeepOut] p3: gap=25 ignorepadtopadclearanceinfootprint=FALSE except(0: SMDPad-Hole THPad-Hole Via-Hole Fill-Hole Poly-Hole Region-Hole Text-Hole; 3: Arc-Fill Arc-Poly Arc-Region Track-Fill Track-Poly Track-Region; 34: Arc-Arc Arc-Track Arc-SMDPad Arc-THPad Arc-Via Arc-Text Arc-Hole Track-Track Track-SMDPad Track-THPad Track-Via Track-Text Track-Hole)
Clearance Clearance_Boardedge_Poly [OnCopper and InPoly vs IsKeepOut] p4: gap=25 ignorepadtopadclearanceinfootprint=FALSE except(0: SMDPad-Hole THPad-Hole Via-Hole Fill-Hole Poly-Hole Region-Hole Text-Hole; 3: Arc-Fill Arc-Poly Arc-Region Track-Fill Track-Poly Track-Region)
Clearance Clearance_Boardedge [OnCopper and Not InComponentClass('Logo') and not InComponentClass('FiducialMark') and not Incomponent ('EC1') and Not IsKeepout vs IsKeepOut] p5: gap=10 ignorepadtopadclearanceinfootprint=FALSE except(0: Arc-Hole Track-Hole SMDPad-Hole THPad-Hole Via-Hole Fill-Hole Poly-Hole Region-Hole Text-Hole; 2.5: Arc-Arc Arc-Track Arc-SMDPad Track-Track Track-SMDPad)
Clearance Clearance_Poly [InPolygon] p6: gap=6 ignorepadtopadclearanceinfootprint=FALSE except(0: Arc-Hole Track-Hole SMDPad-Hole THPad-Hole Via-Hole Fill-Hole Poly-Hole Region-Hole Text-Hole; 7: Arc-THPad Track-THPad SMDPad-THPad THPad-THPad THPad-Via THPad-Fill THPad-Poly THPad-Region THPad-Text; 15: Fill-Fill Fill-Poly Fill-Region Poly-Poly Poly-Region Region-Region)
Clearance Clearance_Fiducial [HasFootprint('Fiducial10-20')] p7: gap=4 ignorepadtopadclearanceinfootprint=TRUE except(0: Arc-SMDPad Arc-Hole Track-Hole SMDPad-Hole THPad-Hole Via-Hole Fill-Hole Poly-Hole Region-Hole Text-Hole)
Clearance Clearance_to_TH [OnLayer('Top Layer') Or OnLayer('Bottom Layer')] p8: gap=4 ignorepadtopadclearanceinfootprint=TRUE except(0: Arc-Hole Track-Hole SMDPad-Hole THPad-Hole Via-Hole Fill-Hole Poly-Hole Region-Hole Text-Hole; 7: Arc-THPad Track-THPad SMDPad-THPad THPad-THPad THPad-Via THPad-Fill THPad-Poly THPad-Region THPad-Text)
Clearance [All] p9: gap=4 ignorepadtopadclearanceinfootprint=TRUE except(0: Arc-Hole Track-Hole SMDPad-Hole THPad-Hole Via-Hole Fill-Hole Poly-Hole Region-Hole Text-Hole)
ComponentClearance ComponentClearance_MountingHoles_FiducialMarks [InComponentClass('Mounting Holes') vs InComponentClass('FiducialMark')] p1: gap=50 collisioncheckmode=3 verticalgap=10 showdistances=FALSE
ComponentClearance ComponentClearance_Shunt [InComponentClass('Header') vs InComponentClass('Shunt')] p2: gap=0 collisioncheckmode=3 verticalgap=0 showdistances=FALSE
ComponentClearance ComponentClearance_Logo [InComponentClass('Logo')] p3: gap=40 collisioncheckmode=3 verticalgap=10 showdistances=FALSE
ComponentClearance ComponentClearance_ScrewToNut [(HasFootprint('NY PMS 440 0025 PH')) vs (HasFootprint('Keystone_1902C'))] p4: gap=5 collisioncheckmode=3 verticalgap=10 showdistances=FALSE
ComponentClearance ComponentClearance_MountingHoles [InComponentClass('Mounting Holes')] p5: gap=250 collisioncheckmode=3 verticalgap=100000 showdistances=FALSE
ComponentClearance ComponentClearance_SmallPassives [HasFootprint('0201*') or HasFootprint('0402*') or HasFootprint('0508') or HasFootprint('0603*') or HasFootprint('0612') or HasFootprint('0805*') or HasFootprint('0815*') or HasFootprint('0830*') or HasFootprint('1206*') or HasFootprint('1210*') or HasFootprint('1808*') or HasFootprint('1812*') or HasFootprint('1825*') or HasFootprint('2010*') or HasFootprint('2220*') or HasFootprint('2225*') or HasFootprint('2512*') or HasFootprint('2728*') or HasFootprint('3518*') vs HasFootprint('0201*') or HasFootprint('0402*') or HasFootprint('0508') or HasFootprint('0603*') or HasFootprint('0612') or HasFootprint('0805*') or HasFootprint('0815*') or HasFootprint('0830*') or HasFootprint('1206*') or HasFootprint('1210*') or HasFootprint('1808*') or HasFootprint('1812*') or HasFootprint('1825*') or HasFootprint('2010*') or HasFootprint('2220*') or HasFootprint('2225*') or HasFootprint('2512*') or HasFootprint('2728*') or HasFootprint('3518*')] p6: gap=10 collisioncheckmode=3 verticalgap=10 showdistances=FALSE
ComponentClearance ComponentClearance_THtoSMT [IsThruComponent vs IsSMTComponent and not Incomponent ('J1') and not Incomponent ('J2') and not Incomponent ('J3') and not Incomponent ('J4')] p7: gap=40 collisioncheckmode=3 verticalgap=30 showdistances=FALSE
ComponentClearance ComponentClearance_THtoTH [IsThruComponent vs IsThruComponent] p8: gap=30 collisioncheckmode=3 verticalgap=30 showdistances=FALSE
ComponentClearance [All] p9: gap=30 collisioncheckmode=3 verticalgap=10 showdistances=FALSE
DiffPairsRouting [All] p1: maxlimit=100 minlimit=10 mostfreqgap=10 toplayer_minwidth=15 toplayer_maxwidth=15 toplayer_prefwidth=15 midlayer1_minwidth=15 midlayer1_maxwidth=15 midlayer1_prefwidth=15 midlayer2_minwidth=15 midlayer2_maxwidth=15 midlayer2_prefwidth=15 midlayer3_minwidth=15 midlayer3_maxwidth=15 midlayer3_prefwidth=15 midlayer4_minwidth=15 midlayer4_maxwidth=15 midlayer4_prefwidth=15 midlayer5_minwidth=15 midlayer5_maxwidth=15 midlayer5_prefwidth=15 midlayer6_minwidth=15 midlayer6_maxwidth=15 midlayer6_prefwidth=15 bottomlayer_minwidth=15 bottomlayer_maxwidth=15 bottomlayer_prefwidth=15 maxuncoupledlength=1000
FabricationTestPointUsage TestPointUsage [All] p1: valid=2 allowmultiple=FALSE
FabricationTestpoint Testpoint [All] p1: side=3 testpointundercomponent=TRUE minsize=40 maxsize=100 preferedsize=60 minholesize=0 maxholesize=40 preferedholesize=32 testpointgrid=1 allowsidetop=TRUE allowsidebottom=TRUE usegrid=TRUE gridtolerance=0.01
FanoutControl Fanout_LCC [IsLCC] p1: bgadir=Out bgaviamode=Centered fanoutstyle=Auto fanoutdirection=Alternating viagrid=1 // Fanout_LCC (Default Rule)
FanoutControl Fanout_BGA [IsBGA] p2: bgadir=Out bgaviamode=Centered fanoutstyle=Auto fanoutdirection=Alternating viagrid=1 // Fanout_BGA (Default Rule)
FanoutControl Fanout_Default [All] p4: bgadir=Out bgaviamode=Centered fanoutstyle=Auto fanoutdirection=Alternating viagrid=1 // Fanout_Default (Default Rule)
FanoutControl Fanout_Small [(CompPinCount < 5)] p5: bgadir=Out bgaviamode=Centered fanoutstyle=Auto fanoutdirection=OutThenIn viagrid=1 // Fanout_Small (Default Rule)
HoleSize [All] p1: absolutevalues=TRUE maxlimit=251 minlimit=7.87 maxpercent=80.000 minpercent=20.000
MinimumAnnularRing MinimumAnnularRing_ThermalPadVias [IsVia and InAnyComponent] p1: minimumring=5.91
MinimumAnnularRing [All] p2: minimumring=7
MinimumSolderMaskSliver MinimumSolderMaskSliver_Logo [InComponentClass('Logo') vs InComponentClass('Logo')] p1: minsoldermaskwidth=0.7
MinimumSolderMaskSliver [All] p2: minsoldermaskwidth=3.94
PlaneClearance PlaneClearance_1 [All] p1: clearance=20
PlaneClearance PlaneClearance_Via [IsVia] p2: clearance=15
PlaneConnect [All] p1: planeconnectstyle=Relief reliefexpansion=10 reliefentries=4 reliefconductorwidth=10 reliefairgap=10
PolygonConnect PolygonConnect_via [isvia] p1: connectstyle=Relief reliefconductorwidth=10 reliefentries=4 polygonreliefangle="45 Angle" airgapwidth=10
PolygonConnect [All] p2: connectstyle=Relief reliefconductorwidth=10 reliefentries=4 polygonreliefangle="90 Angle" airgapwidth=10
RoutingVias ThermalPadVias [IsVia and InAnyComponent] p1: holewidth=8 width=22 viastyle="Through Hole" minholewidth=8 minwidth=22 maxholewidth=12.99 maxwidth=23.62
RoutingVias [All] p2: holewidth=8 width=22 viastyle="Through Hole" minholewidth=8 minwidth=22 maxholewidth=40 maxwidth=65
SilkToBoardRegionClearance [Not ((IsComment or IsDesignator) And (Hide <> 'False')) and not InRegion(1000,500,4000,800)] p1:
SilkToSilkClearance SilkToSilkClearance_Pb-FreeLogo [(HasFootprint('Pb-Free_Overlay_Medium') OR HasFootprint('Pb-Free_Overlay_Small')) vs (HasFootprint('Pb-Free_Overlay_Medium') OR HasFootprint('Pb-Free_Overlay_Small'))] p1: silktosilkclearance=0
SilkToSilkClearance [All] p2: silktosilkclearance=3
SilkToSolderMaskClearance SilkToComponentPadClearance [IsPad and InAnycomponent] p1: minsilkscreentomaskgap=3 clearancetoexposedcopper=TRUE
SilkToSolderMaskClearance "Silk to Solder Mask Opening" [All] p2: minsilkscreentomaskgap=3 clearancetoexposedcopper=FALSE
SolderMaskExpansion [All] p1: expansion=1.97
Width [All] p1: maxlimit=50 minlimit=5 preferedwidth=12 toplayer_prefwidth=6 midlayer1_prefwidth=6 midlayer2_prefwidth=6 midlayer3_prefwidth=6 midlayer4_prefwidth=6 bottomlayer_prefwidth=6 minimp=50.000000 maximp=50.000000 favimp=50.000000 checkconnectedcopper=TRUE
14 further rules are at their usual default settings.

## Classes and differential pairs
component class Label: LBL1
component class Logo: Logo2
component class MCU072A_Hardware: FID1 FID2 FID3 FID4 FID5 FID6 LBL1 Logo1 Logo2 Logo3 LOGO4 ZZ1 ZZ2 ZZ3 ZZ4
component class FiducialMark: FID1 FID2 FID3 FID4 FID5 FID6
component class AssemblyNote: ZZ1 ZZ2 ZZ3 ZZ4
component class MCU072A_ADC: C26 C27 C28 C29 C30 C31 C32 C33 C34 C35 C36 C37 C38 C39 C40 C41 C42 C43 C44 R23 R24 R25 R26 R27 R28 R29 R30 R31 R32 R33 R34 R35 R36 R37 R38 S5 U1 U5 U6 U7 U8
component class MCU072A_GPIO: EC1 J1 R1 R2 R3 R4 R5 R6 R7 R8 R9 R10 S1 S2
component class MCU072A_Emulator_Interface: C19:A C20:A C21:A C22:A C23:A C24:A C25:A C26:A R15:A R16:A S1:A U5:A U6:A U7:A U8:A
component class MCU072A_Power: C1 C2 C3 C4 C5 C6 C7 C8 C9 C10 C11 C12 C13 C14 C15 C16 C17 C18 C19 C20 C21 C22 C23 C24 C25 D1 D2 D3 L1 L2 R11 R12 R13 R14 R15 R16 R17 R18 R19 R20 R21 R22 S3 S4 TP1 TP2 TP3 TP4 TP5 TP6 U2 U3 U4 Y1
component class MCU072A_Emulator_Hardware: C1:A C2:A C3:A C4:A C5:A C6:A C7:A C8:A C9:A C10:A C11:A C12:A C13:A C14:A C15:A C16:A C17:A C18:A D1:A D2:A D3:A D4:A J1:A L1:A L2:A R1:A R2:A R3:A R4:A R5:A R6:A R7:A R8:A R9:A R10:A R11:A R12:A R13:A R14:A TP1:A TP2:A TP3:A U1:A U2:A U3:A U4:A Y1:A

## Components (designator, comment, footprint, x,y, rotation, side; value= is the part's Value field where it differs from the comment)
C1 "GRM188R61A106ME69D" 0603 1400,1204 r0 bottom value=10uF
C1:A "885012105010" 0402 260.2,1258.84 r180 top value=0.1uF
C2 "GRM188R61A106ME69D" 0603 1390,1204 r0 top value=10uF
C2:A "C0603C475K9PACTU" 0603 485,1239 r180 bottom value=4.7uF
C3 "885012105010" 0402 1382,1083 r180 bottom value=0.1uF
C3:A "C0603C475K9PACTU" 0603 265.2,1323.84 r0 top value=4.7uF
C4 "885012105010" 0402 1662.98,865 r270 bottom value=0.1uF
C4:A "0402ZC103KAT2A" 0402 535.2,1623.84 r270 top value=0.01uF
C5 "885012105010" 0402 1411,553 r0 bottom value=0.1uF
C5:A "C0603C475K9PACTU" 0603 -10,1139 r270 top value=4.7uF
C6 "885012105010" 0402 1092,861 r90 bottom value=0.1uF
C6:A "885012105010" 0402 310.2,1188.84 r180 top value=0.1uF
C7 "LMK212ABJ106KG-T" 0805_HV 1847.1,391.4 r90 bottom value=10uF
C7:A "885012105010" 0402 -15,789 r90 top value=0.1uF
C8 "GRM188R61A106ME69D" 0603 1747.1,406.4 r270 bottom value=10uF
C8:A "885012105010" 0402 340,834 r180 top value=0.1uF
C9 "885012105010" 0402 2063.1,1336.4 r270 top value=0.1uF
C9:A "885012105010" 0402 428.7,1022.74 r90 top value=0.1uF
C10 "CGA3E3X5R1A225K080AB" 0603 920,874 r0 bottom value=2.2uF
C10:A "885012105010" 0402 -19.8,913.84 r90 top value=0.1uF
C11 "CGA3E3X5R1A225K080AB" 0603 905,794 r0 bottom value=2.2uF
C11:A "885012105010" 0402 435.2,853.84 r270 top value=0.1uF
C12 "885012105010" 0402 1133,861 r270 bottom value=0.1uF
C12:A "CL05B104KP5NNNC" 0402 200.35,735.34 r180 top value=0.1uF
C13 "885012105010" 0402 1411,512 r180 bottom value=0.1uF
C13:A "C0603C475K9PACTU" 0603 470.54,1456.65 r90 bottom value=4.7uF
C14 "885012105010" 0402 1622,865 r90 bottom value=0.1uF
C14:A "885012105010" 0402 -145,1049 r180 bottom value=0.1uF
C15 "885012105010" 0402 1382,1042 r0 bottom value=0.1uF
C15:A "C0603C475K9PACTU" 0603 85.2,1358.84 r180 bottom value=4.7uF
C16 "885012105010" 0402 1280,531 r180 bottom value=0.1uF
C16:A "885012105010" 0402 105.2,1293.84 r0 bottom value=0.1uF
C17 "885012005056" 0402 1921,1032 r270 bottom value=15pF
C17:A "C0402C270J5GACTU" 0402 -204.8,1088.84 r90 top value=27pF
C18 "885012005056" 0402 1785,1032 r90 bottom value=15pF
C18:A "C0402C270J5GACTU" 0402 -50,1289 r270 bottom value=27pF
C19 "GRM188R61A106ME69D" 0603 2254,823.76 r90 bottom value=10uF
C19:A "885012105010" 0402 535,1623 r90 bottom value=0.1uF
C20 "885012105010" 0402 2120,797.76 r0 bottom value=0.1uF
C20:A "885012105010" 0402 980,1619 r270 bottom value=0.1uF
C21 "0402ZC103KAT2A" 0402 2174,988.76 r270 top value=0.01uF
C21:A "885012105010" 0402 655.99,1356.64 r90 bottom value=0.1uF
C22 "GRM188R61A106ME69D" 0603 2102,1007.25 r270 top value=10uF
C22:A "885012105010" 0402 895,1352.62 r270 bottom value=0.1uF
C23 "0402ZC103KAT2A" 0402 1658,1294 r270 bottom value=0.01uF
C23:A "885012105010" 0402 897,978 r270 bottom value=0.1uF
C24 "0402ZC103KAT2A" 0402 1850,1294 r90 top value=0.01uF
C24:A "885012105010" 0402 648,981 r270 bottom value=0.1uF
C25 "885012105010" 0402 1771.6,1279.1 r90 bottom value=0.1uF
C25:A "885012105010" 0402 1670,1585 r270 bottom value=0.1uF
C26 "885012105010" 0402 628,304 r270 top value=0.1uF
C26:A "C1812C100JHGACTU" 1812_180 776,1601 r180 bottom value=10pF
C27 "885012105010" 0402 374,318 r270 top value=0.1uF
C28 "CGA3E3X5R1A225K080AB" 0603 1146.5,543 r180 bottom value=2.2uF
C29 "GRM188R71C104KA01D" 0603 82,160 r90 top value=0.1uF
C30 "GRM188R71C104KA01D" 0603 314.29,160 r90 top value=0.1uF
C31 "GRM188R71C104KA01D" 0603 86,474 r270 top value=0.1uF
C32 "GRM188R71C104KA01D" 0603 315.29,474 r270 top value=0.1uF
C33 "GRM188R71C104KA01D" 0603 315.86,474 r270 bottom value=0.1uF
C34 "GRM188R71C104KA01D" 0603 87,474 r270 bottom value=0.1uF
C35 "GRM188R71C104KA01D" 0603 623.93,160 r90 bottom value=0.1uF
C36 "GRM188R71C104KA01D" 0603 621,474 r270 top value=0.1uF
C37 "GRM188R71C104KA01D" 0603 624,160 r90 top value=0.1uF
C38 "GRM188R71C104KA01D" 0603 621,474 r270 bottom value=0.1uF
C39 "GRM188R71C104KA01D" 0603 391.65,160 r90 top value=0.1uF
C40 "GRM188R71C104KA01D" 0603 391.65,160 r90 bottom value=0.1uF
C41 "GRM188R71C104KA01D" 0603 391.71,474 r270 top value=0.1uF
C42 "GRM188R71C104KA01D" 0603 314.22,160 r90 bottom value=0.1uF
C43 "GRM188R71C104KA01D" 0603 81.93,160 r90 bottom value=0.1uF
C44 "GRM188R71C104KA01D" 0603 392.14,474 r270 bottom value=0.1uF
D1 "150080SS75000" WL-SMCW_RED_0805 2125,1537 r90 top value=Red
D1:A "MBRM110ET1G" POWERMITE 230.2,1493.84 r90 top value=10V
D2 "150080SS75000" WL-SMCW_RED_0805 2212,1537 r90 top value=Red
D2:A "150080VS75000" WL-SMCW_Green_0805 405.58,1637.56 r180 top value="Bright Green"
D3 "150080VS75000" WL-SMCW_Green_0805 2254,908.64 r270 top value="Bright Green"
D3:A "150080BS75000" WL-SMCW_Blue_0805 -209.8,827.46 r90 top value=Blue
D4:A "150080BS75000" WL-SMCW_Blue_0805 -113.01,827.64 r90 top value=Blue
EC1 "controlCARD-120HSEC_Edge" controlCARD-120HSEC_Edge 970.2,-245.16 r0 top
FID1 "Fiducial" Fiducial10-20 -215,322 r90 top
FID2 "Fiducial" Fiducial10-20 2093,85 r0 top
FID3 "Fiducial" Fiducial10-20 2032,1658 r0 top
FID4 "Fiducial" Fiducial10-20 -215,322 r90 bottom
FID5 "Fiducial" Fiducial10-20 2093,85 r90 bottom
FID6 "Fiducial" Fiducial10-20 -206.9,1656.4 r90 bottom
J1 "TMM-105-01-T-D" FP-TMM-105-01-T-D_HDR10-MFG 2212.37,459.48 r270 top
J1:A "65100516121" Wurth_65100516121 -284.78,1454.87 r270 top
L1 "BLM21PG221SN1D" 0805_HV 1799,419 r180 top value="220 ohm"
L1:A "HZ0805E601R-10" 0805_HV 347.57,1464.29 r90 bottom value="600 ohm"
L2 "BKP2125HS600-T" 0805_HV 925,828 r270 top value="60 ohm"
L2:A "HZ0805E601R-10" 0805_HV 35.2,1438.84 r180 bottom value="600 ohm"
LBL1 "THT-14-423-10" Label_650x200 1407,701 r0 bottom
Logo1 "CE Mark" CE_Mark_5mm 1856,158 r180 bottom
Logo2 "Texas Instruments" TI_Stacked_Overlay_Small 1209,325 r180 bottom
Logo3 "FCC disclaimer" FCC_disclaimer 2329,1108 r90 bottom
LOGO4 "WEEE logo" WEEE_Minimum 905,640 r180 bottom (schematic designator Logo4)
R1 "CRCW04024K70JNED" 0402 5.31,160 r270 top value=4.7k
R1:A "CRCW0402680RJNED" 0402 381.47,1636.91 r180 bottom value=680
R2 "CRCW04024K70JNED" 0402 5.51,159.65 r90 bottom value=4.7k
R2:A "CRCW040210K0JNED" 0402 580.99,1279.64 r180 top value=10k
R3 "CRCW06030000Z0EA" 0603 2053,617 r0 bottom value=0
R3:A "CRCW04020000Z0ED" 0402 370,1304 r90 bottom value=0
R4 "CRCW06030000Z0EA" 0603 2053,537 r0 bottom value=0
R4:A "CRCW040210K0JNED" 0402 545,889 r0 bottom value=10k
R5 "CRCW06030000Z0EA" 0603 2053,617 r0 top value=0
R5:A "CRCW04021K00JNED" 0402 545.2,808.84 r0 bottom value=1.0k
R6 "CRCW06030000Z0EA" 0603 2053,457 r0 bottom value=0
R6:A "CRCW04021K00JNED" 0402 -211,804 r270 bottom value=1.0k
R7 "CRCW06030000Z0EA" 0603 2053,308 r0 bottom value=0
R7:A "CRCW04021K00JNED" 0402 -111,802 r270 bottom value=1.0k
R8 "CRCW06030000Z0EA" 0603 1519,141 r270 bottom value=0
R8:A "CRCW040210K0JNED" 0402 118.12,831 r90 top value=10k
R9 "CRCW06030000Z0EA" 0603 1573,141 r270 bottom value=0
R9:A "CRCW04022K20JNED" 0402 49,921 r90 top value=2.2k
R10 "CRCW06030000Z0EA" 0603 2053,382 r0 bottom value=0
R10:A "CRCW04021K00JNED" 0402 321,1307 r270 bottom value=1.0k
R11 "CRCW0402820RJNED" 0402 2115,1571 r270 bottom value=820
R11:A "CRCW04020000Z0ED" 0402 -144,1435 r0 bottom value=0
R12 "CRCW0402820RJNED" 0402 2216,1571 r270 bottom value=820
R12:A "CRCW04020000Z0ED" 0402 -95,1089 r270 top value=0
R13 "CRCW04021M50JNED" 0402 2125,1313 r90 bottom value=1.5Meg
R13:A "CRCW040212K0JNED" 0402 115,1243.84 r0 bottom value=12k
R14 "CRCW04021M50JNED" 0402 2206,1313 r90 bottom value=1.5Meg
R14:A "CRCW04020000Z0ED" 0402 331,732 r180 top value=0
R15 "CRCW08050000Z0EA" 0805_HV 2011,852.76 r270 top value=0
R15:A "CRCW040210K0JNED" 0402 1223.1,1469.4 r90 bottom value=10k
R16 "CRCW0402510RJNED" 0402 2129,893.04 r180 bottom value=510
R16:A "CRCW040210K0JNED" 0402 1278.1,1469.4 r90 bottom value=10k
R17 "CRCW040256K0JNED" 0402 1800,1500 r270 bottom value=56k
R18 "CRCW040256K0JNED" 0402 1946,1500 r90 bottom value=56k
R19 "CRCW04022K20JNED" 0402 1585,1294 r90 bottom value=2.2k
R20 "CRCW04020000Z0ED" 0402 1587,1294 r270 top value=0
R21 "CRCW04022K20JNED" 0402 1849,1293 r270 bottom value=2.2k
R22 "CRCW04022K20JNED" 0402 1547,1500 r90 bottom value=2.2k
R23 "CRCW06030000Z0EA" 0603 159.43,160 r90 top value=0
R24 "CRCW06030000Z0EA" 0603 236.86,160 r90 top value=0
R25 "CRCW06030000Z0EA" 0603 162.43,474 r270 top value=0
R26 "CRCW06030000Z0EA" 0603 238.86,474 r270 top value=0
R27 "CRCW06030000Z0EA" 0603 239.57,474 r270 bottom value=0
R28 "CRCW06030000Z0EA" 0603 163.29,474 r270 bottom value=0
R29 "CRCW06030000Z0EA" 0603 546.51,160 r90 bottom value=0
R30 "CRCW06030000Z0EA" 0603 544.57,474 r270 top value=0
R31 "CRCW06030000Z0EA" 0603 546.57,160 r90 top value=0
R32 "CRCW06030000Z0EA" 0603 544.71,474 r270 bottom value=0
R33 "CRCW06030000Z0EA" 0603 469.08,160 r90 top value=0
R34 "CRCW06030000Z0EA" 0603 469.08,160 r90 bottom value=0
R35 "CRCW06030000Z0EA" 0603 468.14,474 r270 top value=0
R36 "CRCW06030000Z0EA" 0603 236.79,160 r90 bottom value=0
R37 "CRCW06030000Z0EA" 0603 159.36,160 r90 bottom value=0
R38 "CRCW06030000Z0EA" 0603 468.43,474 r270 bottom value=0
S1 "CAS-D20TA" SW_CAS-D20TA 1288.1,234.46 r0 top
S1:A "218-2LPST" SW_218-2LP 1248.1,1506.4 r90 top
S2 "CAS-D20TA" SW_CAS-D20TA 1665,234.46 r0 top
S3 "CAS-220TA" SW_CAS-220TA 1857,806.54 r0 top
S4 "CAS-D20TA" SW_CAS-D20TA 1873,1501.03 r0 top
S5 "CAS-D20TA" SW_CAS-D20TA 858,515 r180 top
TP1 "TESTPOINT" TP_50MIL-25MILHOLE -102.4,506 r0 top
TP1:A "TESTPOINT" TP_50MIL-25MILHOLE -102.4,693 r90 top
TP2 "TESTPOINT" TP_50MIL-25MILHOLE 2272,1232 r90 top
TP2:A "TESTPOINT" TP_50MIL-25MILHOLE -204.8,692.84 r90 top
TP3 "TESTPOINT" TP_50MIL-25MILHOLE 1180,1199 r0 top
TP3:A "TESTPOINT" TP_50MIL-25MILHOLE 0,691 r90 top
TP4 "TESTPOINT" TP_50MIL-25MILHOLE 0,506 r0 top
TP5 "TESTPOINT" TP_50MIL-25MILHOLE 1939,1172 r90 top
TP6 "TESTPOINT" TP_50MIL-25MILHOLE 1939,1322 r0 top
U1 "TMX320F280025CPNSR" PN0080A_N 1378.21,795.76 r0 top
U1:A "TPS73033DBVR" DBV0005A_N 405.2,1453.84 r90 top
U2 "SN74LVC2G07DBVR" DBV0006A_N 2165.91,1344.87 r90 top
U2:A "FT2232HL-REEL" LQFP64_N 226.22,954.87 r270 bottom
U3 "TPS73633DBVR" DBV0005A_N 2136,843.76 r90 top
U3:A "TPD2E001DRLR" DRL0005A 185.2,1448.84 r180 bottom
U4 "TPS3702CX33DDCR" DDC0006A_N 1716.6,1279.1 r0 top
U4:A "93LC56C-I/SN" SOIC-8 225.2,973.84 r0 top
U5 "TPD4E001QDBVRQ1" DBV0006A_N 199.1,315.4 r90 top
U5:A "ISO7220CD" D0008B_N 776.22,1554.87 r0 top
U6 "TPD4E001QDBVRQ1" DBV0006A_N 504,321 r90 bottom
U6:A "ISO7220CD" D0008B_N 776.22,1304.87 r0 top
U7 "TPD4E001QDBVRQ1" DBV0006A_N 198,314 r270 bottom
U7:A "SN74ALVC244PWR" PW0020A_N 1549,1503 r0 top
U8 "TPD4E001QDBVRQ1" DBV0006A_N 505.64,322.87 r90 top
U8:A "ISO7220CD" D0008B_N 777,1034 r180 top
Y1 "ECS-200-18-30B-AGN-TR" ECS_ECX-53B 1858.33,1032.83 r270 top
Y1:A "12MHz" ECS_ECX-53B -159.8,1193.84 r0 bottom
ZZ1 "This Assembly Note is for PCB labels only" AssemblyNoteLabel -1305.9,2509.96 r0 top
ZZ2 "These assemblies are ESD sensitive, ESD precautions shall be observed." AssemblyNote -1307,2410 r0 top
ZZ3 "These assemblies must be clean and free from flux and all contaminants. Use of no clean flux is not acceptable." AssemblyNote -1304.6,2333.9 r0 top
ZZ4 "These assemblies must comply with workmanship standards IPC-A-610 Class 2, unless otherwise specified." AssemblyNote -1309,2229 r0 top

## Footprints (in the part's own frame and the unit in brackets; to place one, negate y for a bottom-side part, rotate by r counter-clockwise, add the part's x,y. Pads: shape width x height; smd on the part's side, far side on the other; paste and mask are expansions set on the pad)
0402 [mm] "0402 from SM-752 data"
  rect 0.8x0.6 smd: 1(-0.6,0) 2(0.6,0)
  silkscreen extent -1.22,-0.52 1.22,0.52, body extent -0.55,-0.3 0.55,0.3, height 0.6
0603 [mm] "0603 from SM-752 data"
  rect 1x0.95 smd: 1(-0.8,0) 2(0.8,0)
  silkscreen extent -1.52,-0.69 1.52,0.69, body extent -0.87,-0.47 0.87,0.47, height 1
0805_HV [mil] "0805 with 30mil clearance between pads"
  rect 50x63 smd: 1(-40,0) 2(40,0)
  silkscreen extent -74,-40 74,40, body extent -43,-29 43,29, height 57
1812_180 [mm] "SMT, 2-Leads, Body 4.5x3.2mm"
  rect 1.85x4.36 smd: 1(-2.53,0) 2(2.53,0)
  silkscreen extent -3.75,-2.48 3.75,2.48, body extent -2.43,-1.75 2.42,1.75, height 1.8
AssemblyNote [mil] "Assembly Note"
AssemblyNoteLabel [mil] "Assembly Note for PCB Labels"
CE_Mark_5mm [mil] "Minimum text height for CE Mark"
  silkscreen extent -138,-98 138,98
controlCARD-120HSEC_Edge [mm] "Edge Connector, 0.8mm, 60x2, pad numbers do not match Samtec datasheet"
  rect 0.55x2.8 smd paste-2.5 mask+0: 1(-23.6,2.4) 3(-22.8,2.4) 5(-22,2.4) 7(-21.2,2.4) 9(-20.4,2.4) 11(-19.6,2.4) 13(-18.8,2.4) 15(-18,2.4) 17(-17.2,2.4) 19(-16.4,2.4) 21(-15.6,2.4) 23(-14.8,2.4) 25(-14,2.4) 27(-13.2,2.4) 29(-12.4,2.4) 31(-11.6,2.4) 33(-10.8,2.4) 35(-10,2.4) 37(-9.2,2.4) 39(-8.4,2.4) 41(-7.6,2.4) 43(-6.8,2.4) 45(-6,2.4) 47(-5.2,2.4) 49(-4.4,2.4) 51(-3.6,2.4) 53(-2.8,2.4) 55(-2,2.4) 57(2,2.4) 59(2.8,2.4) 61(3.6,2.4) 63(4.4,2.4) 65(5.2,2.4) 67(6,2.4) 69(6.8,2.4) 71(7.6,2.4) 73(8.4,2.4) 75(9.2,2.4) 77(10,2.4) 79(10.8,2.4) 81(11.6,2.4) 83(12.4,2.4) 85(13.2,2.4) 87(14,2.4) 89(14.8,2.4) 91(15.6,2.4) 93(16.4,2.4) 95(17.2,2.4) 97(18,2.4) 99(18.8,2.4) 101(19.6,2.4) 103(20.4,2.4) 105(21.2,2.4) 107(22,2.4) 109(22.8,2.4) 111(23.6,2.4) 113(24.4,2.4) 115(25.2,2.4) 117(26,2.4) 119(26.8,2.4)
  rect 0.55x2.8 smd far side paste-2.5 mask+0: 2(-23.6,2.4) 4(-22.8,2.4) 6(-22,2.4) 8(-21.2,2.4) 10(-20.4,2.4) 12(-19.6,2.4) 14(-18.8,2.4) 16(-18,2.4) 18(-17.2,2.4) 20(-16.4,2.4) 22(-15.6,2.4) 24(-14.8,2.4) 26(-14,2.4) 28(-13.2,2.4) 30(-12.4,2.4) 32(-11.6,2.4) 34(-10.8,2.4) 36(-10,2.4) 38(-9.2,2.4) 40(-8.4,2.4) 42(-7.6,2.4) 44(-6.8,2.4) 46(-6,2.4) 48(-5.2,2.4) 50(-4.4,2.4) 52(-3.6,2.4) 54(-2.8,2.4) 56(-2,2.4) 58(2,2.4) 60(2.8,2.4) 62(3.6,2.4) 64(4.4,2.4) 66(5.2,2.4) 68(6,2.4) 70(6.8,2.4) 72(7.6,2.4) 74(8.4,2.4) 76(9.2,2.4) 78(10,2.4) 80(10.8,2.4) 82(11.6,2.4) 84(12.4,2.4) 86(13.2,2.4) 88(14,2.4) 90(14.8,2.4) 92(15.6,2.4) 94(16.4,2.4) 96(17.2,2.4) 98(18,2.4) 100(18.8,2.4) 102(19.6,2.4) 104(20.4,2.4) 106(21.2,2.4) 108(22,2.4) 110(22.8,2.4) 112(23.6,2.4) 114(24.4,2.4) 116(25.2,2.4) 118(26,2.4) 120(26.8,2.4)
D0008B_N [mil] "SOIC, 8-Leads, Body 4.9x3.9mm, Pitch 1.27mm, IPC Medium Density"
  oval 55x23.62 smd: 1(-108.5,75) 2(-108.5,25) 3(-108.5,-25) 4(-108.5,-75) 5(108.5,-75) 6(108.5,-25) 7(108.5,25) 8(108.5,75)
  silkscreen extent -130,-98 35,98, body extent -118,-96 118,96, height 64
DBV0005A_N [mm] "SOT23, 5-Leads, Body 2.9x1.6mm, Pitch 0.95mm, Lead Span 2.8mm, IPC Medium Density"
  rrect17% 1x0.6 smd: 1(-1.375,0.95) 2(-1.375,0) 3(-1.375,-0.95) 4(1.375,-0.95) 5(1.375,0.95)
  silkscreen extent -0.25,-1.55 0.25,1.55, body extent -1.42,-1.46 1.42,1.46, height 1.09
DBV0006A_N [mm] "SOT23, 6-Leads, Body 2.9x1.6mm, Pitch 0.95mm, Lead Span 2.8mm, IPC Medium Density"
  rrect17% 1x0.6 smd: 1(-1.375,0.95) 2(-1.375,0) 3(-1.375,-0.95) 4(1.375,-0.95) 5(1.375,0) 6(1.375,0.95)
  silkscreen extent -1.68,-1.55 0.5,1.55, body extent -1.42,-1.46 1.42,1.46, height 1.12
DDC0006A_N [mm]
  rrect17% 1x0.6 smd: 1(-1.375,0.95) 2(-1.375,0) 3(-1.375,-0.95) 4(1.375,-0.95) 5(1.375,0) 6(1.375,0.95)
  silkscreen extent -1.75,-1.52 0.7,1.53, body extent -1.43,-1.48 1.43,1.49, height 0.92
DRL0005A [mm] "SOTFL, 5-Flat Leads, Body 1.2x1.6x0.6mm, Pitch 0.5mm, TI recommended"
  rrect33% 0.67x0.3 smd: 1(-0.74,0.5) 2(-0.74,0) 3(-0.74,-0.5) 4(0.74,-0.5) 5(0.74,0.5)
  silkscreen extent -0.9,-0.95 0.5,0.95, body extent -0.85,-0.85 0.85,0.85, height 0.62
ECS_ECX-53B [mm] "SMD, 4-Leads, Body 5x3.2mm"
  rect 1.25x1.6 smd: 1(-1.1,1.85) 2(-1.1,-1.85) 3(1.1,-1.85) 4(1.1,1.85)
  silkscreen extent -2.05,-2.7 1.83,2.73, body extent -1.7,-2.6 1.7,2.6, height 0.86
FCC_disclaimer [mil]
Fiducial10-20 [mm]
  round 1 smd mask+0.5: 1(0,0)
  Top Layer keep-out circle w1.178: c0,0 r0.5
FP-TMM-105-01-T-D_HDR10-MFG [mm]
  rrect7% 1.39x1.39 hole 0.89 paste-1000 mask+0: 1(-4,-1)
  round 1.39 hole 0.89 paste-1000 mask+0: 2(-4,1) 3(-2,-1) 4(-2,1) 5(0,-1) 6(0,1) 7(2,-1) 8(2,1) 9(4,-1) 10(4,1)
  body extent -5.1,-2.13 5.1,2.13, height 0.25
Label_650x200 [mil] "Thermal Transfer Label"
  round 1 on Mech14: 0(0,0)
  silkscreen extent -325,-100 325,100, body extent -325,-100 325,100, height 1
LQFP64_N [mm] "Thin QFP, 64-Leads, Body 10x10mm, Pitch 0.5mm, IPC Medium Density"
  oval 1.8x0.3 smd: 1(-5.55,3.75) 2(-5.55,3.25) 3(-5.55,2.75) 4(-5.55,2.25) 5(-5.55,1.75) 6(-5.55,1.25) 7(-5.55,0.75) 8(-5.55,0.25) 9(-5.55,-0.25) 10(-5.55,-0.75) 11(-5.55,-1.25) 12(-5.55,-1.75) 13(-5.55,-2.25) 14(-5.55,-2.75) 15(-5.55,-3.25) 16(-5.55,-3.75) 33(5.55,-3.75) 34(5.55,-3.25) 35(5.55,-2.75) 36(5.55,-2.25) 37(5.55,-1.75) 38(5.55,-1.25) 39(5.55,-0.75) 40(5.55,-0.25) 41(5.55,0.25) 42(5.55,0.75) 43(5.55,1.25) 44(5.55,1.75) 45(5.55,2.25) 46(5.55,2.75) 47(5.55,3.25) 48(5.55,3.75)
  oval 0.3x1.8 smd: 17(-3.75,-5.55) 18(-3.25,-5.55) 19(-2.75,-5.55) 20(-2.25,-5.55) 21(-1.75,-5.55) 22(-1.25,-5.55) 23(-0.75,-5.55) 24(-0.25,-5.55) 25(0.25,-5.55) 26(0.75,-5.55) 27(1.25,-5.55) 28(1.75,-5.55) 29(2.25,-5.55) 30(2.75,-5.55) 31(3.25,-5.55) 32(3.75,-5.55) 49(3.75,5.55) 50(3.25,5.55) 51(2.75,5.55) 52(2.25,5.55) 53(1.75,5.55) 54(1.25,5.55) 55(0.75,5.55) 56(0.25,5.55) 57(-0.25,5.55) 58(-0.75,5.55) 59(-1.25,5.55) 60(-1.75,5.55) 61(-2.25,5.55) 62(-2.75,5.55) 63(-3.25,5.55) 64(-3.75,5.55)
  silkscreen extent -5.67,-4.25 4.25,4.57, body extent -5,-5 5,5, height 1.6
PN0080A_N [mm] "QFP, 80-Leads, Body 12x12mm, Pitch 0.5mm, IPC Medium Density"
  oval 1.45x0.3 smd: 1(-6.725,4.75) 2(-6.725,4.25) 3(-6.725,3.75) 4(-6.725,3.25) 5(-6.725,2.75) 6(-6.725,2.25) 7(-6.725,1.75) 8(-6.725,1.25) 9(-6.725,0.75) 10(-6.725,0.25) 11(-6.725,-0.25) 12(-6.725,-0.75) 13(-6.725,-1.25) 14(-6.725,-1.75) 15(-6.725,-2.25) 16(-6.725,-2.75) 17(-6.725,-3.25) 18(-6.725,-3.75) 19(-6.725,-4.25) 20(-6.725,-4.75) 41(6.725,-4.75) 42(6.725,-4.25) 43(6.725,-3.75) 44(6.725,-3.25) 45(6.725,-2.75) 46(6.725,-2.25) 47(6.725,-1.75) 48(6.725,-1.25) 49(6.725,-0.75) 50(6.725,-0.25) 51(6.725,0.25) 52(6.725,0.75) 53(6.725,1.25) 54(6.725,1.75) 55(6.725,2.25) 56(6.725,2.75) 57(6.725,3.25) 58(6.725,3.75) 59(6.725,4.25) 60(6.725,4.75)
  oval 0.3x1.45 smd: 21(-4.75,-6.725) 22(-4.25,-6.725) 23(-3.75,-6.725) 24(-3.25,-6.725) 25(-2.75,-6.725) 26(-2.25,-6.725) 27(-1.75,-6.725) 28(-1.25,-6.725) 29(-0.75,-6.725) 30(-0.25,-6.725) 31(0.25,-6.725) 32(0.75,-6.725) 33(1.25,-6.725) 34(1.75,-6.725) 35(2.25,-6.725) 36(2.75,-6.725) 37(3.25,-6.725) 38(3.75,-6.725) 39(4.25,-6.725) 40(4.75,-6.725) 61(4.75,6.725) 62(4.25,6.725) 63(3.75,6.725) 64(3.25,6.725) 65(2.75,6.725) 66(2.25,6.725) 67(1.75,6.725) 68(1.25,6.725) 69(0.75,6.725) 70(0.25,6.725) 71(-0.25,6.725) 72(-0.75,6.725) 73(-1.25,6.725) 74(-1.75,6.725) 75(-2.25,6.725) 76(-2.75,6.725) 77(-3.25,6.725) 78(-3.75,6.725) 79(-4.25,6.725) 80(-4.75,6.725)
  silkscreen extent -6.85,-5.6 5.6,5.6, body extent -7,-7 7,7, height 1.56
POWERMITE [mil] "On Semi recommended land pattern, 457-04.pdf Rev 04E dated 2008-11-26"
  rect 105x100 smd: 1(-46,0)
  rect 30x50 smd: 2(46,0)
  silkscreen extent -124,-63 61,63, body extent -94,-40 59,40, height 45
PW0020A_N [mm] "TSOP, 20-Leads, Body 6.5x4.4mm, Pitch 0.65mm, IPC Medium Density"
  oval 1.4x0.45 smd: 1(-2.95,2.925) 2(-2.95,2.275) 3(-2.95,1.625) 4(-2.95,0.975) 5(-2.95,0.325) 6(-2.95,-0.325) 7(-2.95,-0.975) 8(-2.95,-1.625) 9(-2.95,-2.275) 10(-2.95,-2.925) 11(2.95,-2.925) 12(2.95,-2.275) 13(2.95,-1.625) 14(2.95,-0.975) 15(2.95,-0.325) 16(2.95,0.325) 17(2.95,0.975) 18(2.95,1.625) 19(2.95,2.275) 20(2.95,2.925)
  Top Overlay keep-out lines w0.2: -1.85,-3.3 1.85,-3.3
  silkscreen extent -3.5,-3.3 1.85,3.4, body extent -3.21,-3.25 3.21,3.25, height 1
SOIC-8 [mm] "duplicate of SO-8.  SOIC, 8-Leads, Body 5.0x4.0mm (max), Pitch 1.27mm, IPC Medium Density"
  rrect17% 1.45x0.6 smd: 1(-2.725,1.905) 2(-2.725,0.635) 3(-2.725,-0.635) 4(-2.725,-1.905) 5(2.725,-1.905) 6(2.725,-0.635) 7(2.725,0.635) 8(2.725,1.905)
  silkscreen extent -3.5,-2.5 0.9,2.5, body extent -3,-2.45 3,2.45, height 1.63
SW_218-2LP [mm] "SMD, 4-Leads, Body 3.71x5.8mm, Pitch 1.27mm"
  rect 1.27x0.76 smd: 1(-3.81,0.635) 2(-3.81,-0.635) 3(3.81,-0.635) 4(3.81,0.635)
  silkscreen extent -2.9,-1.86 2.9,2.09, body extent -4.22,-1.86 4.22,1.85, height 2.62
SW_CAS-220TA [mm] "COPAL ELECTRONICS"
  rect 1.6x1 smd: 1(-1.85,1.75) 2(-1.85,0) 3(-1.85,-1.75) 4(1.85,1.75) 5(1.85,0) 6(1.85,-1.75)
  silkscreen extent -2.1,-2.9 2,3.7, body extent -2.1,-2.85 2.1,2.85, height 2.51
SW_CAS-D20TA [mm] "SMD, 6-Leads, Body 5.4x3.9mm, Pitch 1.75mm"
  rect 1.6x1 smd: 1(-1.85,1.75) 2(-1.85,0) 3(-1.85,-1.75) 4(1.85,1.75) 5(1.85,0) 6(1.85,-1.75)
  silkscreen extent -1.95,-2.7 1.95,2.9, body extent -2.1,-2.7 2.1,2.7, height 2.5
TI_Stacked_Overlay_Small [mil]
  silkscreen extent -418,-98 418,98
TP_50MIL-25MILHOLE [mil]
  round 50 hole 25: 1(0,0)
WEEE_Minimum [mil] "WEEElie bin"
  silkscreen extent -95,-172 99,104
WL-SMCW_Blue_0805 [mm] "SMD, 2-Leads, Body 2x1.25mm"
  rect 1.1x1.2 smd: 1(-1.05,0) 2(1.05,0)
  silkscreen extent -2.4,-1.1 1.5,1.1, body extent -1,-0.62 1,0.63, height 0.7
WL-SMCW_Green_0805 [mm] "SMD, 2-Leads, Body 2x1.25mm"
  rect 1.1x1.2 smd: 1(-1.05,0) 2(1.05,0)
  silkscreen extent -2.4,-1.1 1.5,1.1, body extent -1,-0.62 1,0.63, height 0.7
WL-SMCW_RED_0805 [mm] "SMD, 2-Leads, Body 1.6x0.8mm"
  rect 1.1x1.2 smd: 1(-1.05,0) 2(1.05,0)
  silkscreen extent -2.4,-1.1 1.5,1.1, body extent -1,-0.62 1,0.63, height 0.7
Wurth_65100516121 [mm] "Connector, Receptacle, USB Mini B 2.0, 5 Position, SMT"
  rect 0.5x2.5 smd: 1(-1.6,8.5) 2(-0.8,8.5) 3(0,8.5) 4(0.8,8.5) 5(1.6,8.5)
  rect 2x2.5 smd: 6(-4.4,8.5) 7(4.4,8.5) 8(-4.4,3) 9(4.4,3)
  round 0.9 hole 0.9 unplated mask+0: ALIGN1(-2.2,5.9) ALIGN2(2.2,5.9)
  silkscreen extent -3.85,0.15 3.85,9.6, body extent -4.8,0 4.8,9.25, height 3.91

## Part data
C1 C2 C8 C19 C22: library part CMP-0007318-5, "CAP, CERM, 10 uF, 10 V, +/- 20%, X5R, 0603", Cap_Case=0603, Manufacturer=MuRata, TempCo=X5R, Tolerance_%=20%, Value1=Unknown, Value2=10V, ValueDisplayed=10uF
C1:A C3 C4 C5 C6 C6:A C7:A C8:A C9 C9:A C10:A C11:A C12 C13 C14 C14:A C15 C16 C16:A C19:A C20 C20:A C21:A C22:A C23:A C24:A C25 C25:A C26 C27: library part CMP-0006221-2, "CAP, CERM, 0.1 uF, 10 V, +/- 20%, X5R, 0402", Cap_Case=0402, Manufacturer="Wurth Elektronik", Supplier Part Number 1=732-7487-1-ND, TempCo=X5R, Tolerance_%=20%, Value1=Unknown, Value2=10V, ValueDisplayed=0.1uF
C2:A C3:A C5:A C13:A C15:A: library part CMP-0006950-5, "CAP, CERM, 4.7 uF, 6.3 V, +/- 10%, X5R, 0603", Cap_Case=0603, Manufacturer=Kemet, Supplier Part Number 1=399-3482-1-ND, TempCo=X5R, Tolerance_%=10%, Value1="0.006 ohm", Value2=6.3V, ValueDisplayed=4.7uF
C4:A C21 C23 C24: library part CMP-0006203-2, "CAP, CERM, 0.01 uF, 10 V, +/- 10%, X7R, 0402", Cap_Case=0402, Manufacturer=AVX, Supplier Part Number 1=478-7890-1-ND, TempCo=X7R, Tolerance_%=10%, Value1=Unknown, Value2=10V, ValueDisplayed=0.01uF
C7: library part CMP-0008395-2, "CAP, CERM, 10 uF, 10 V, +/- 10%, X5R, 0805", Cap_Case=0805, Manufacturer="Taiyo Yuden", Supplier Part Number 1=05X8343, TempCo=X5R, Tolerance_%=10%, Value1=Unknown, Value2=10V, ValueDisplayed=10uF
C10 C11 C28: library part CMP-0007091-5, "CAP, CERM, 2.2 uF, 10 V, +/- 10%, X5R, AEC-Q200 Grade 3, 0603", Cap_Case=0603, Manufacturer=TDK, Supplier Part Number 1=445-12444-1-ND, TempCo=X5R, Tolerance_%=10%, Value1=Unknown, Value2=10V, ValueDisplayed=2.2uF
C12:A: library part CMP-0006343-2, "CAP, CERM, 0.1 uF, 10 V, +/- 10%, X7R, 0402", Cap_Case=0402, Manufacturer="Samsung Electro-Mechanics", TempCo=X7R, Tolerance_%=10%, Value1=Unknown, Value2=10V, ValueDisplayed=0.1uF
C17 C18: library part CMP-0006216-2, "CAP, CERM, 15 pF, 50 V, +/- 5%, C0G/NP0, 0402", Cap_Case=0402, Manufacturer="Wurth Elektronik", Supplier Part Number 1=710-885012005056, TempCo=C0G/NP0, Tolerance_%=5%, Value1=Unknown, Value2=50V, ValueDisplayed=15pF
C17:A C18:A: library part CMP-0750098-1, "CAP, CERM, 27 pF, 50 V,+/- 5%, C0G/NP0, 0402", Cap_Case=0402, Manufacturer=Kemet, TempCo=C0G/NP0, Tolerance_%=5%, Value2=50V, ValueDisplayed=27pF
C26:A: library part CMP-0082066-1, "CAP, CERM, 10 pF, 3000 V,+/- 5%, C0G/NP0, AEC-Q200 Grade 1, 1812", Cap_Case=1812, Manufacturer=Kemet, Supplier Part Number 1=399-7113-1-ND, TempCo=C0G/NP0, Tolerance_%=5%, Value2=3000V, ValueDisplayed=10pF
C29 C30 C31 C32 C33 C34 C35 C36 C37 C38 C39 C40 C41 C42 C43 C44: library part CMP-0007378-5, "CAP, CERM, 0.1 uF, 16 V, +/- 10%, X7R, 0603", Cap_Case=0603, Manufacturer=MuRata, Supplier Part Number 1=490-1532-1-ND, TempCo=X7R, Tolerance_%=10%, Value1=Unknown, Value2=16V, ValueDisplayed=0.1uF
D1 D2: library part CMP-0002951-3, "LED, Red, SMD", Color=Red, Manufacturer="Wurth Elektronik", Power_TotalModule=72mW, Value1=0.072W, Value2=1.9V
D1:A: library part CMP-0028747-2, "Diode, Schottky, 10 V, 1 A, AEC-Q101, POWERMITE", Manufacturer="ON Semiconductor", Value1=1A, Value2=0.53V
D2:A D3: library part CMP-0002960-2, "LED, Bright Green, SMD", Color="Bright Green", Manufacturer="Wurth Elektronik", Power_TotalModule=72mW, Supplier Part Number 1=732-4986-1-ND, Value1=0.072W, Value2=2V
D3:A D4:A: library part CMP-0002959-3, "LED, Blue, SMD", Color=Blue, Manufacturer="Wurth Elektronik", Power_TotalModule=105mW, Value1=0.105W, Value2=3.2V
EC1: library part CMP-0003813-2, "C2000 controlCARD-120HSEC Edge Connector for Samtec HSEC8-160-01-L-DV-A-BL", Manufacturer=Any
